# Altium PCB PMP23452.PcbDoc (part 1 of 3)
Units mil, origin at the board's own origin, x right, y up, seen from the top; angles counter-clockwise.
Board outline 4000 x 4000 mil, 6 copper layers (Top Layer, Layer 2, Layer 3, Layer 4, Layer 5, Bottom Layer), stack 40.224 mil thick; 235 components, 68 nets, 526 pads, 358 vias.
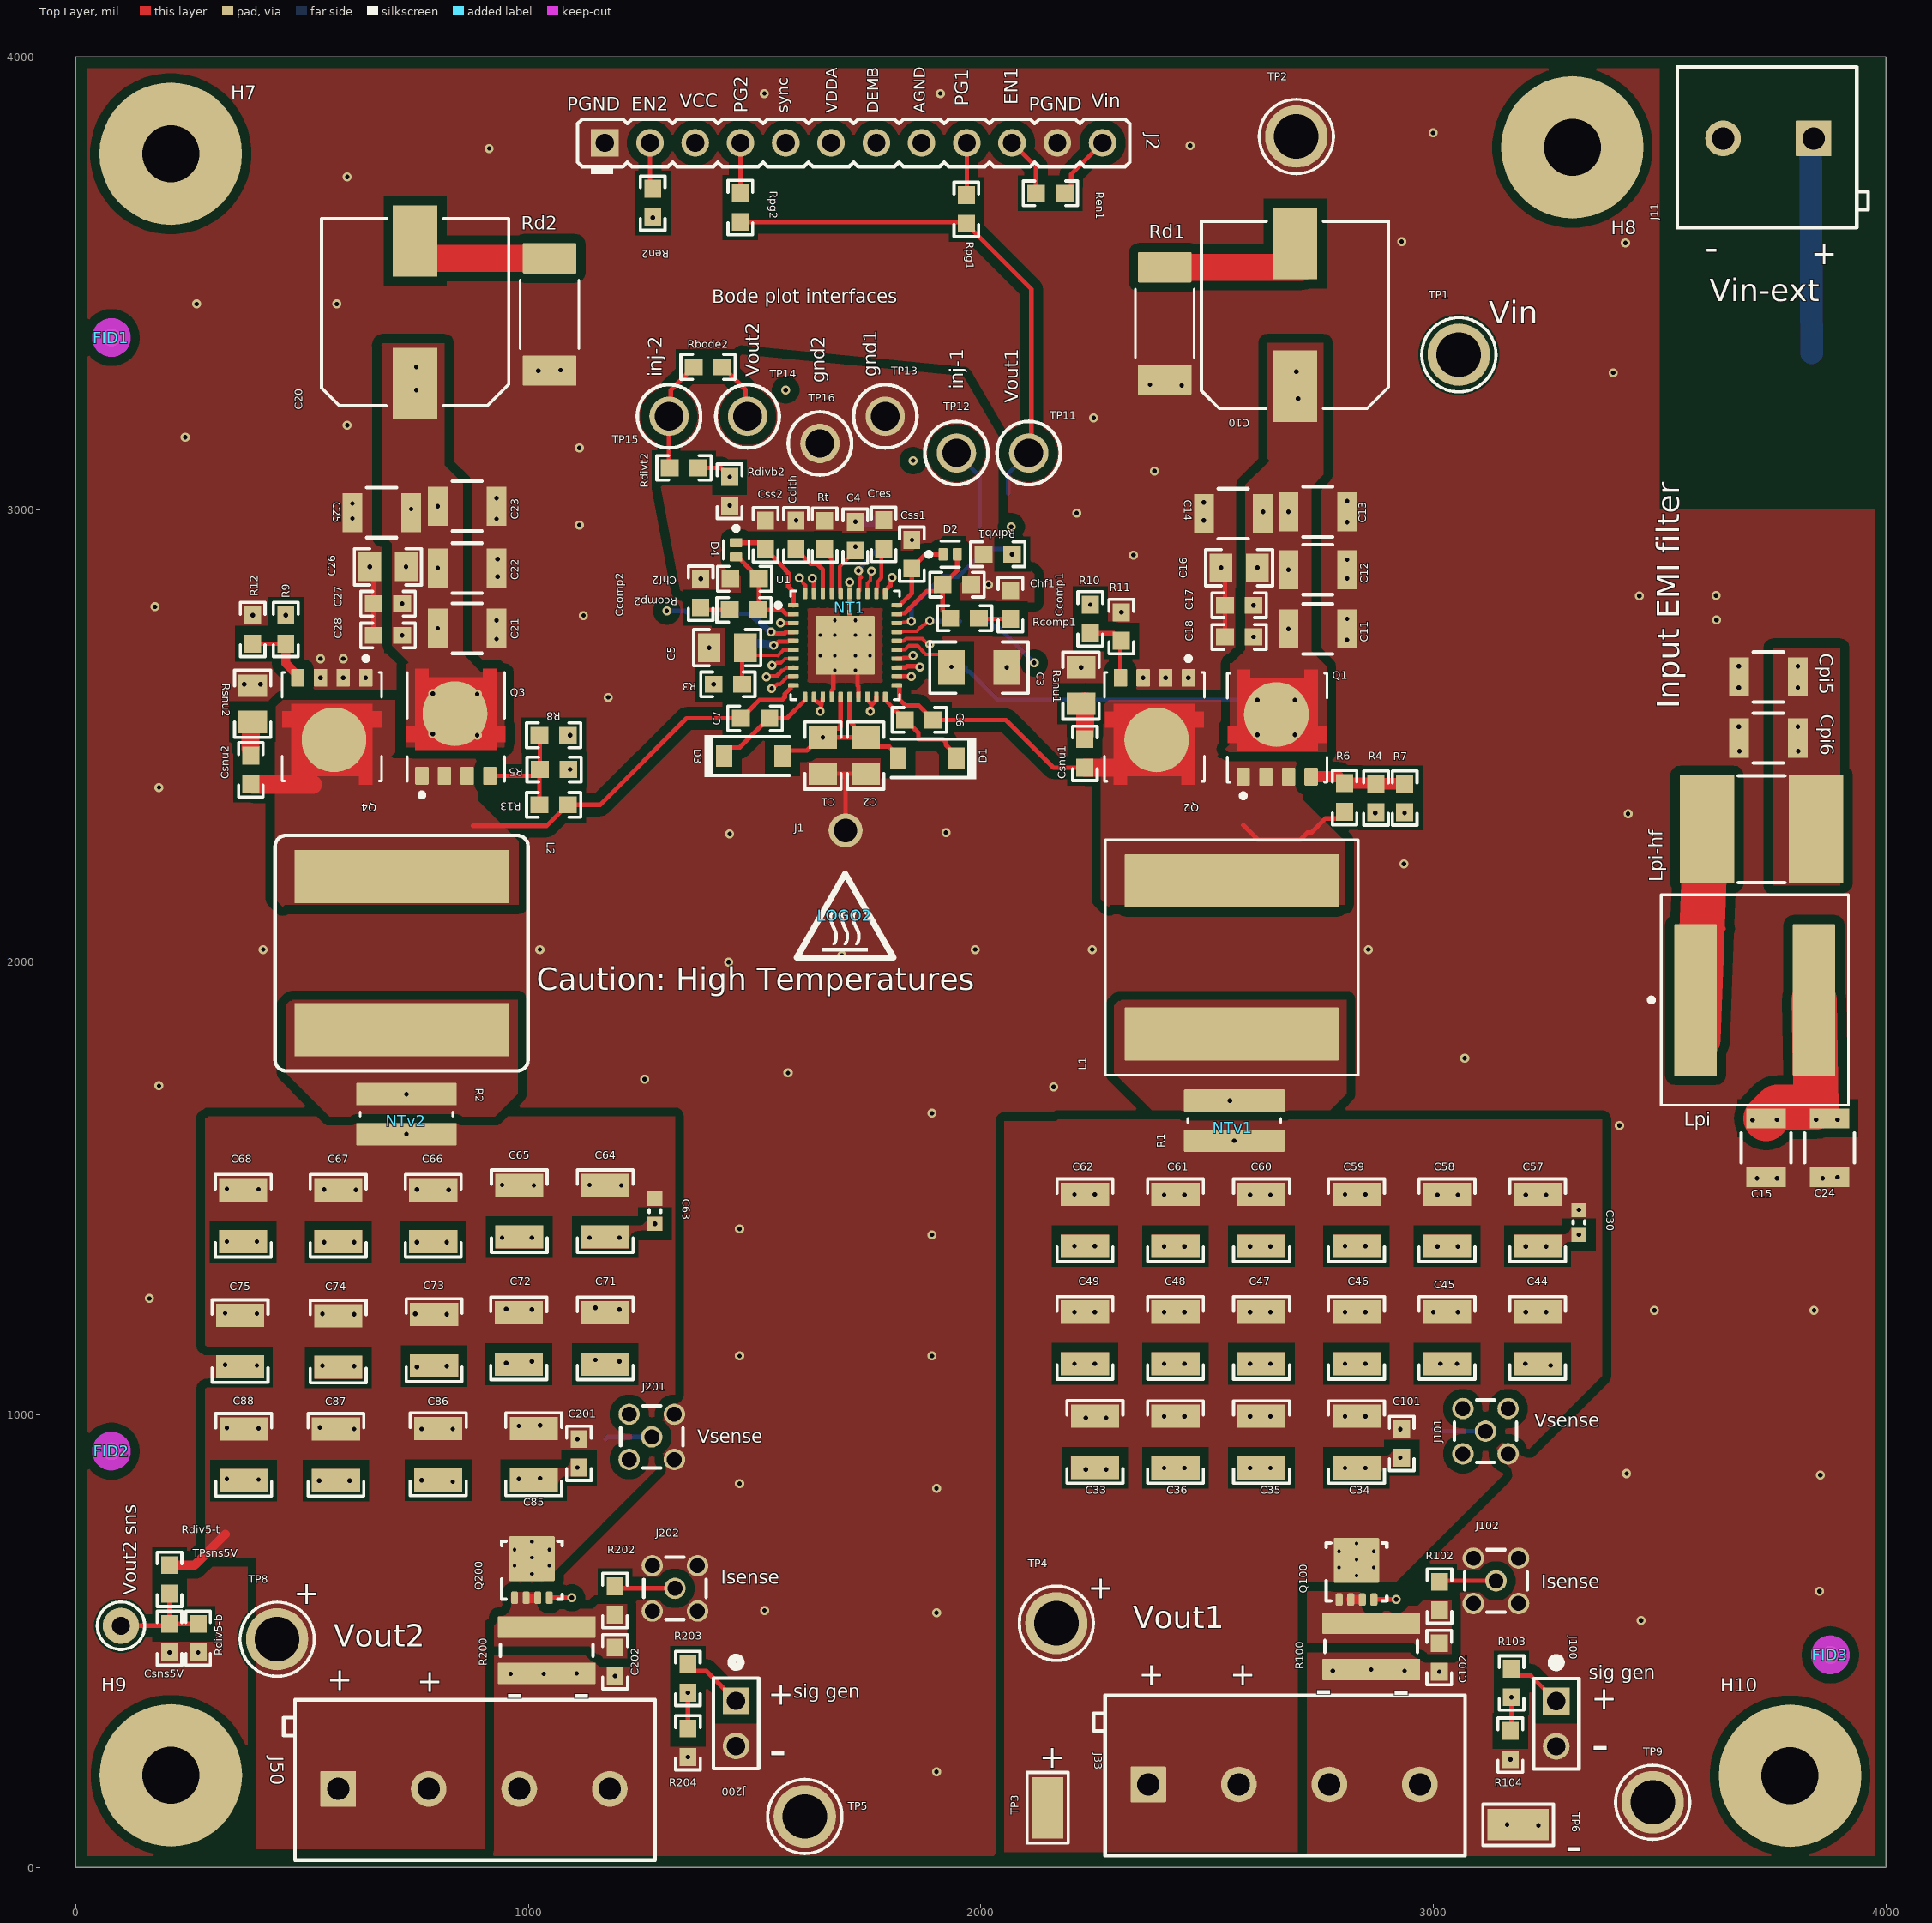
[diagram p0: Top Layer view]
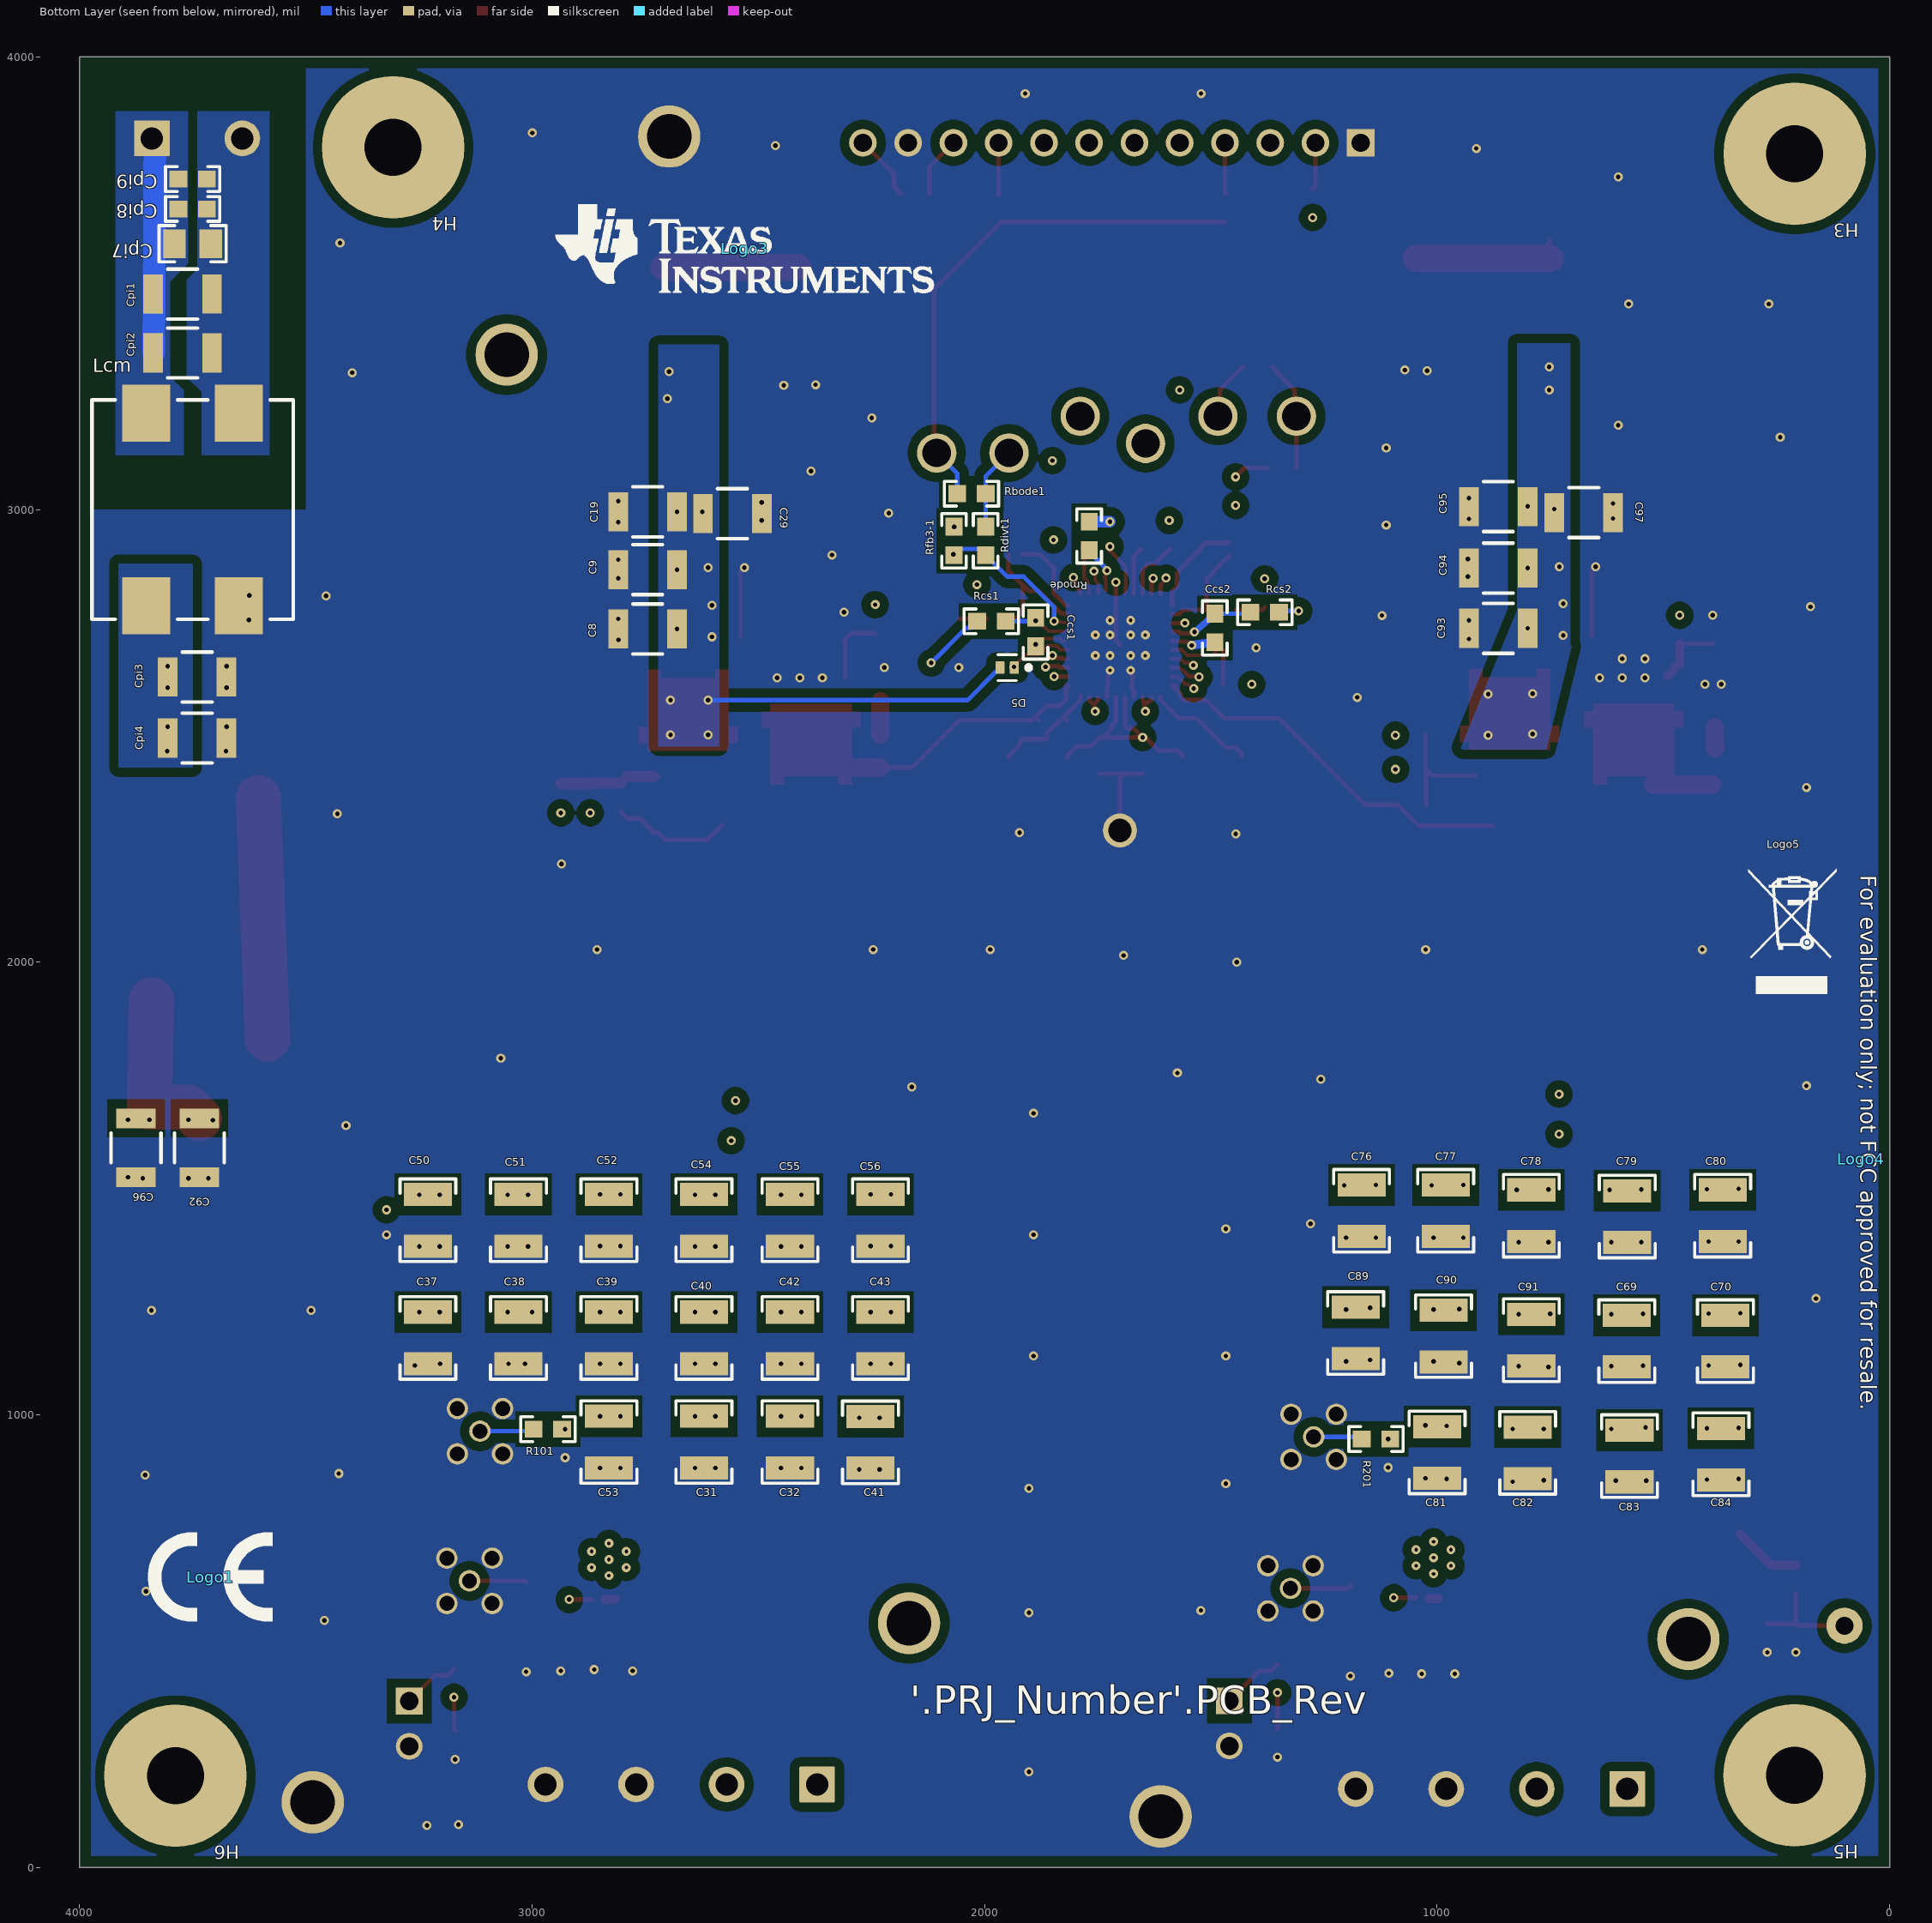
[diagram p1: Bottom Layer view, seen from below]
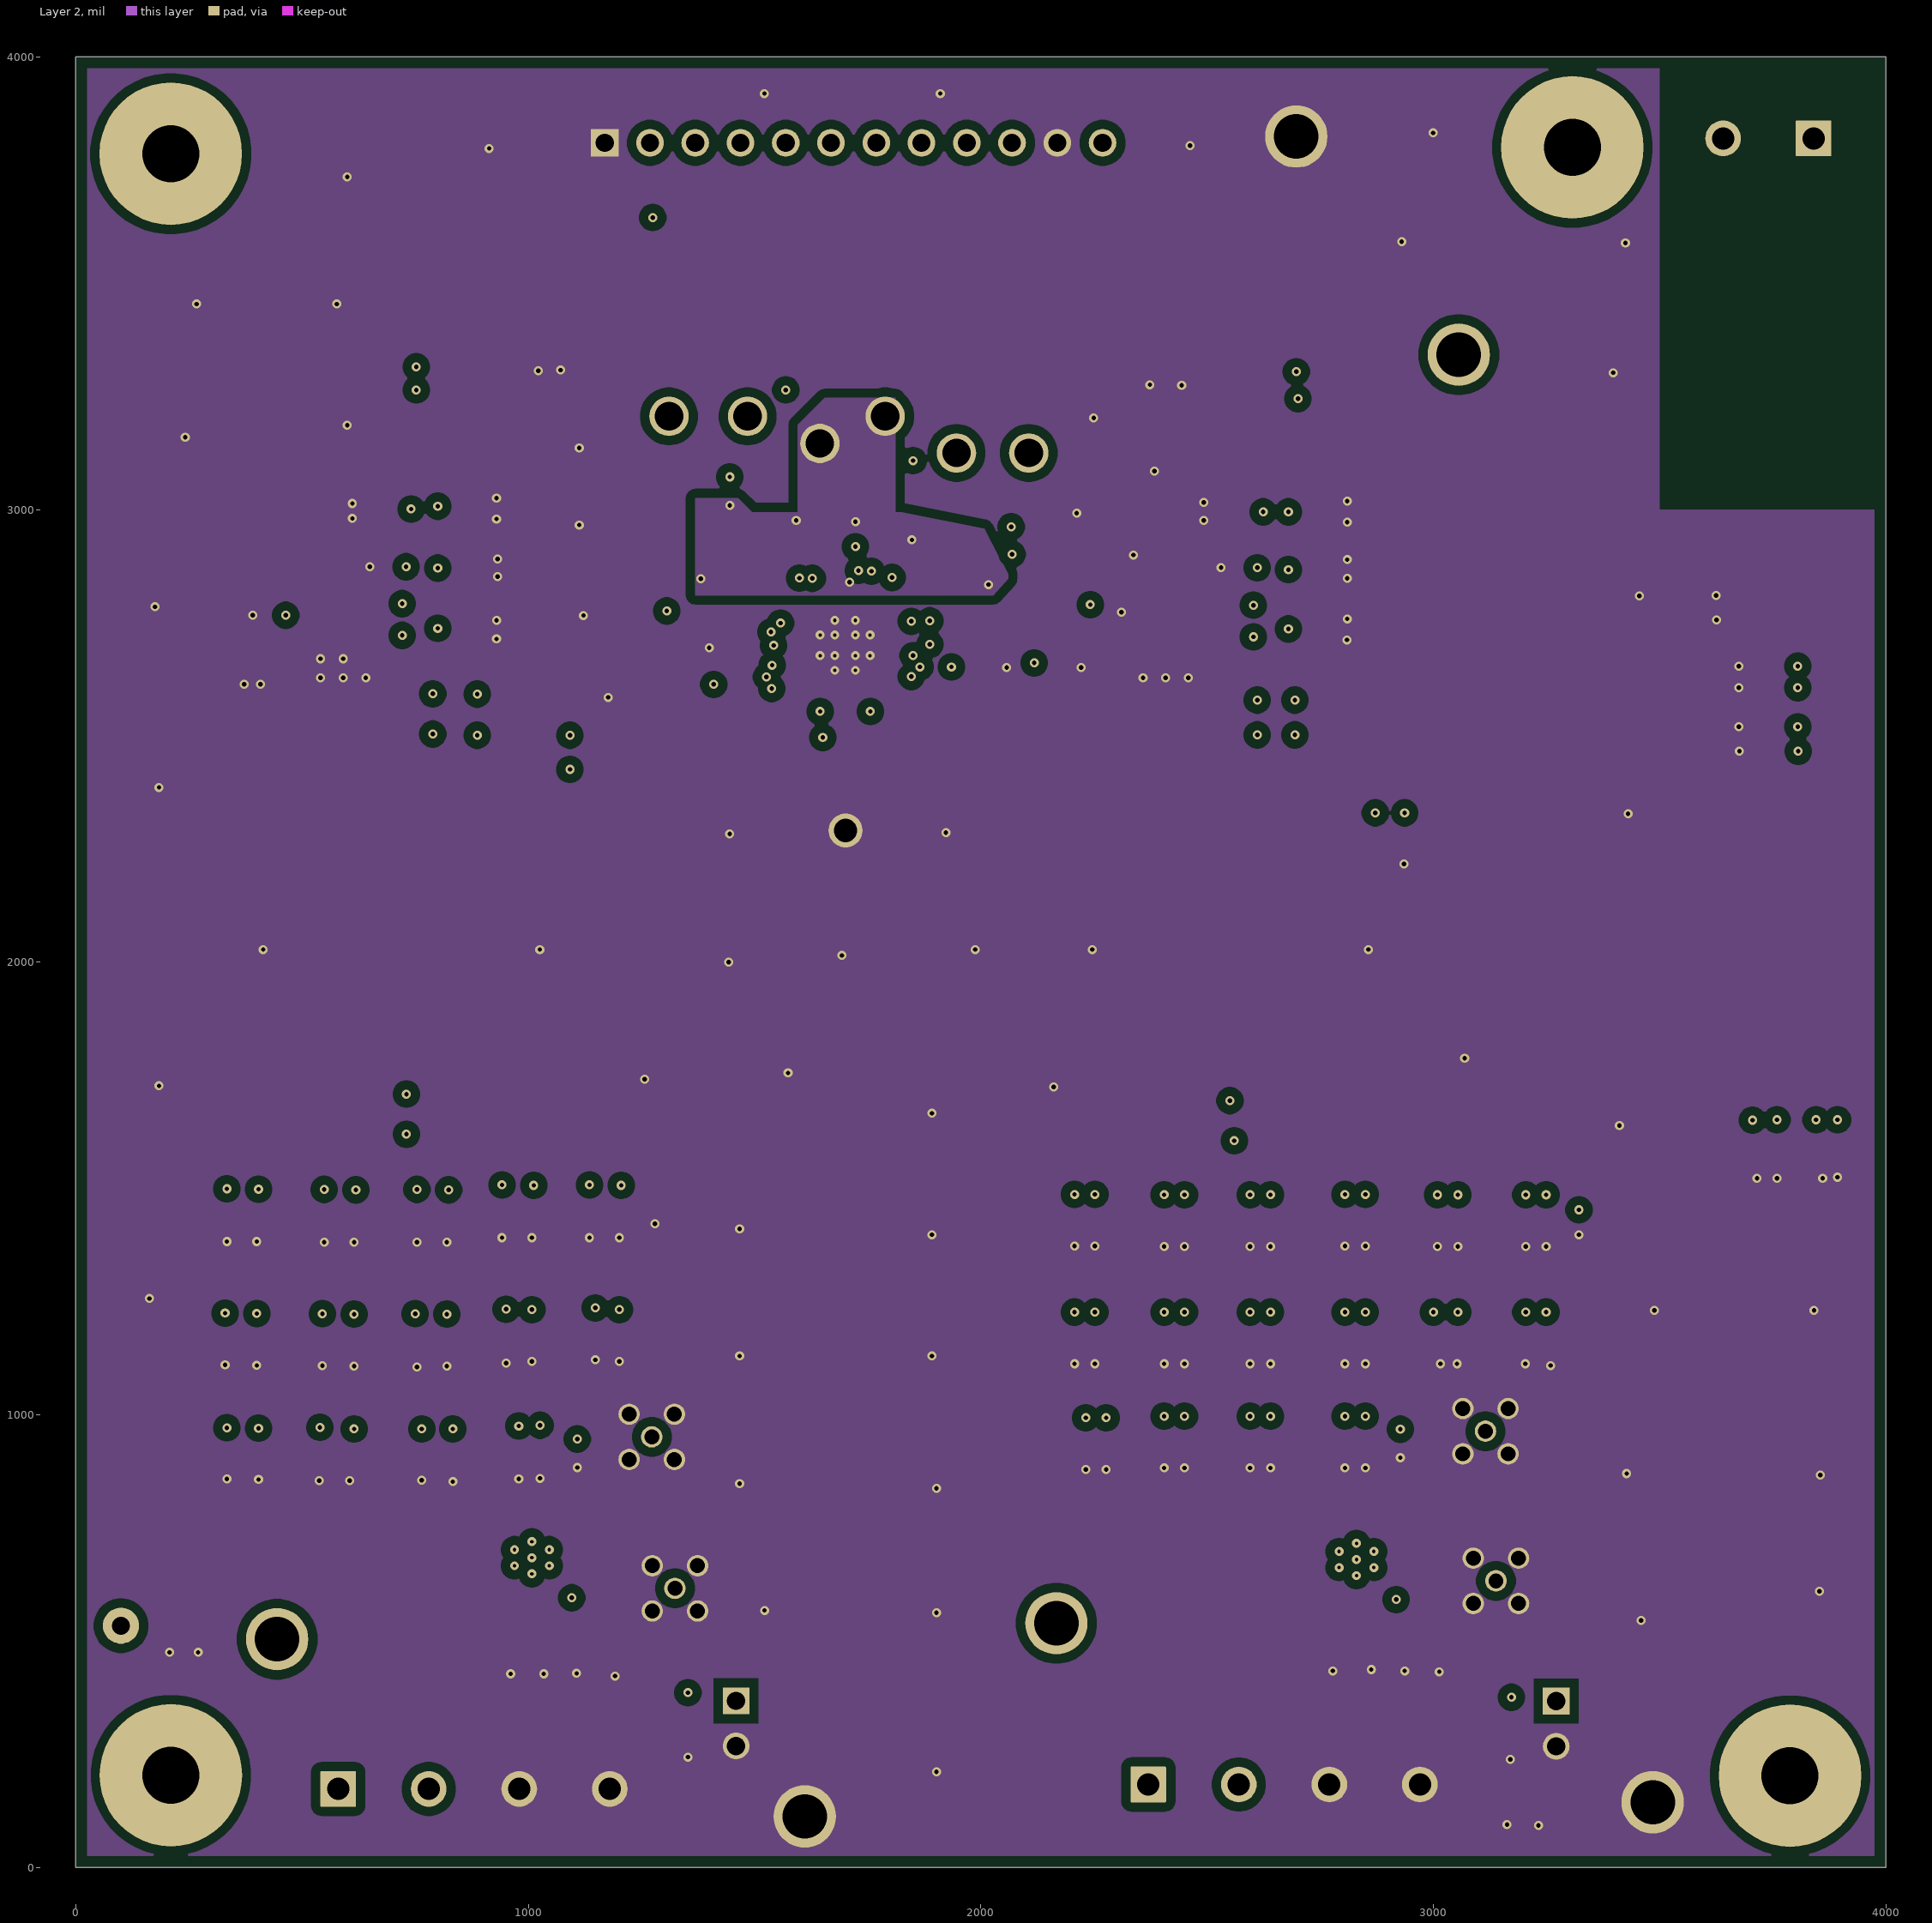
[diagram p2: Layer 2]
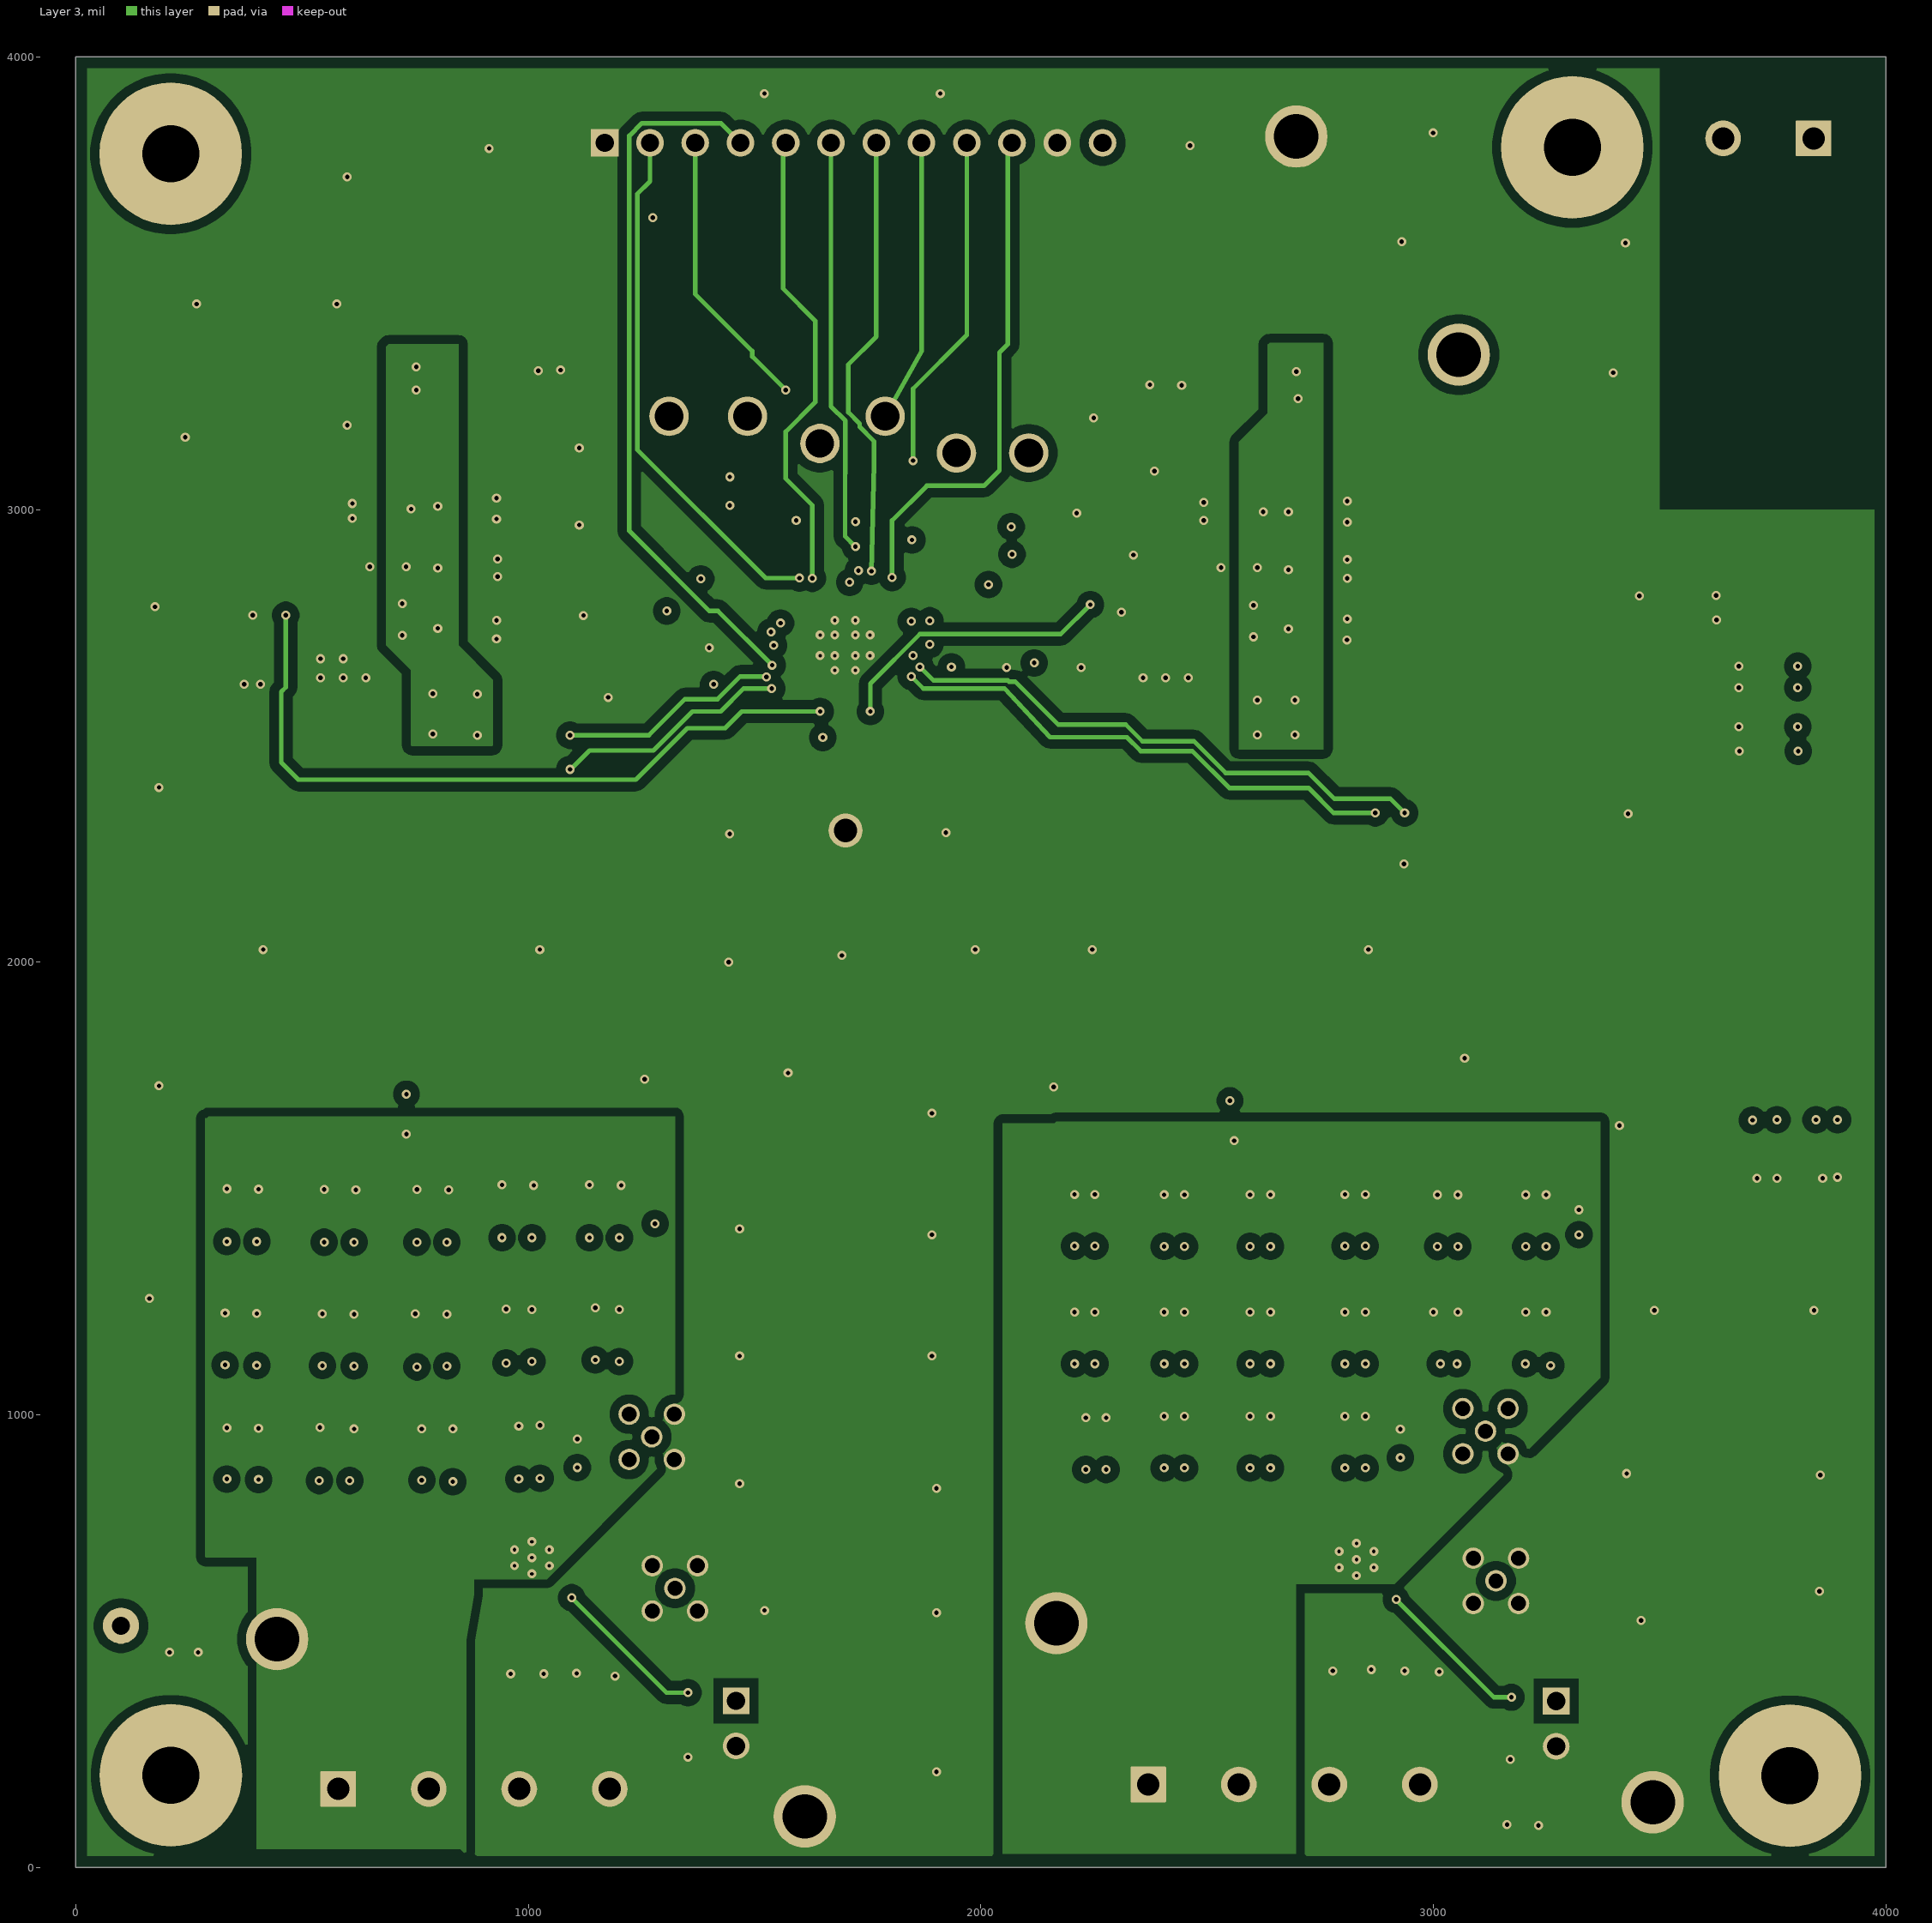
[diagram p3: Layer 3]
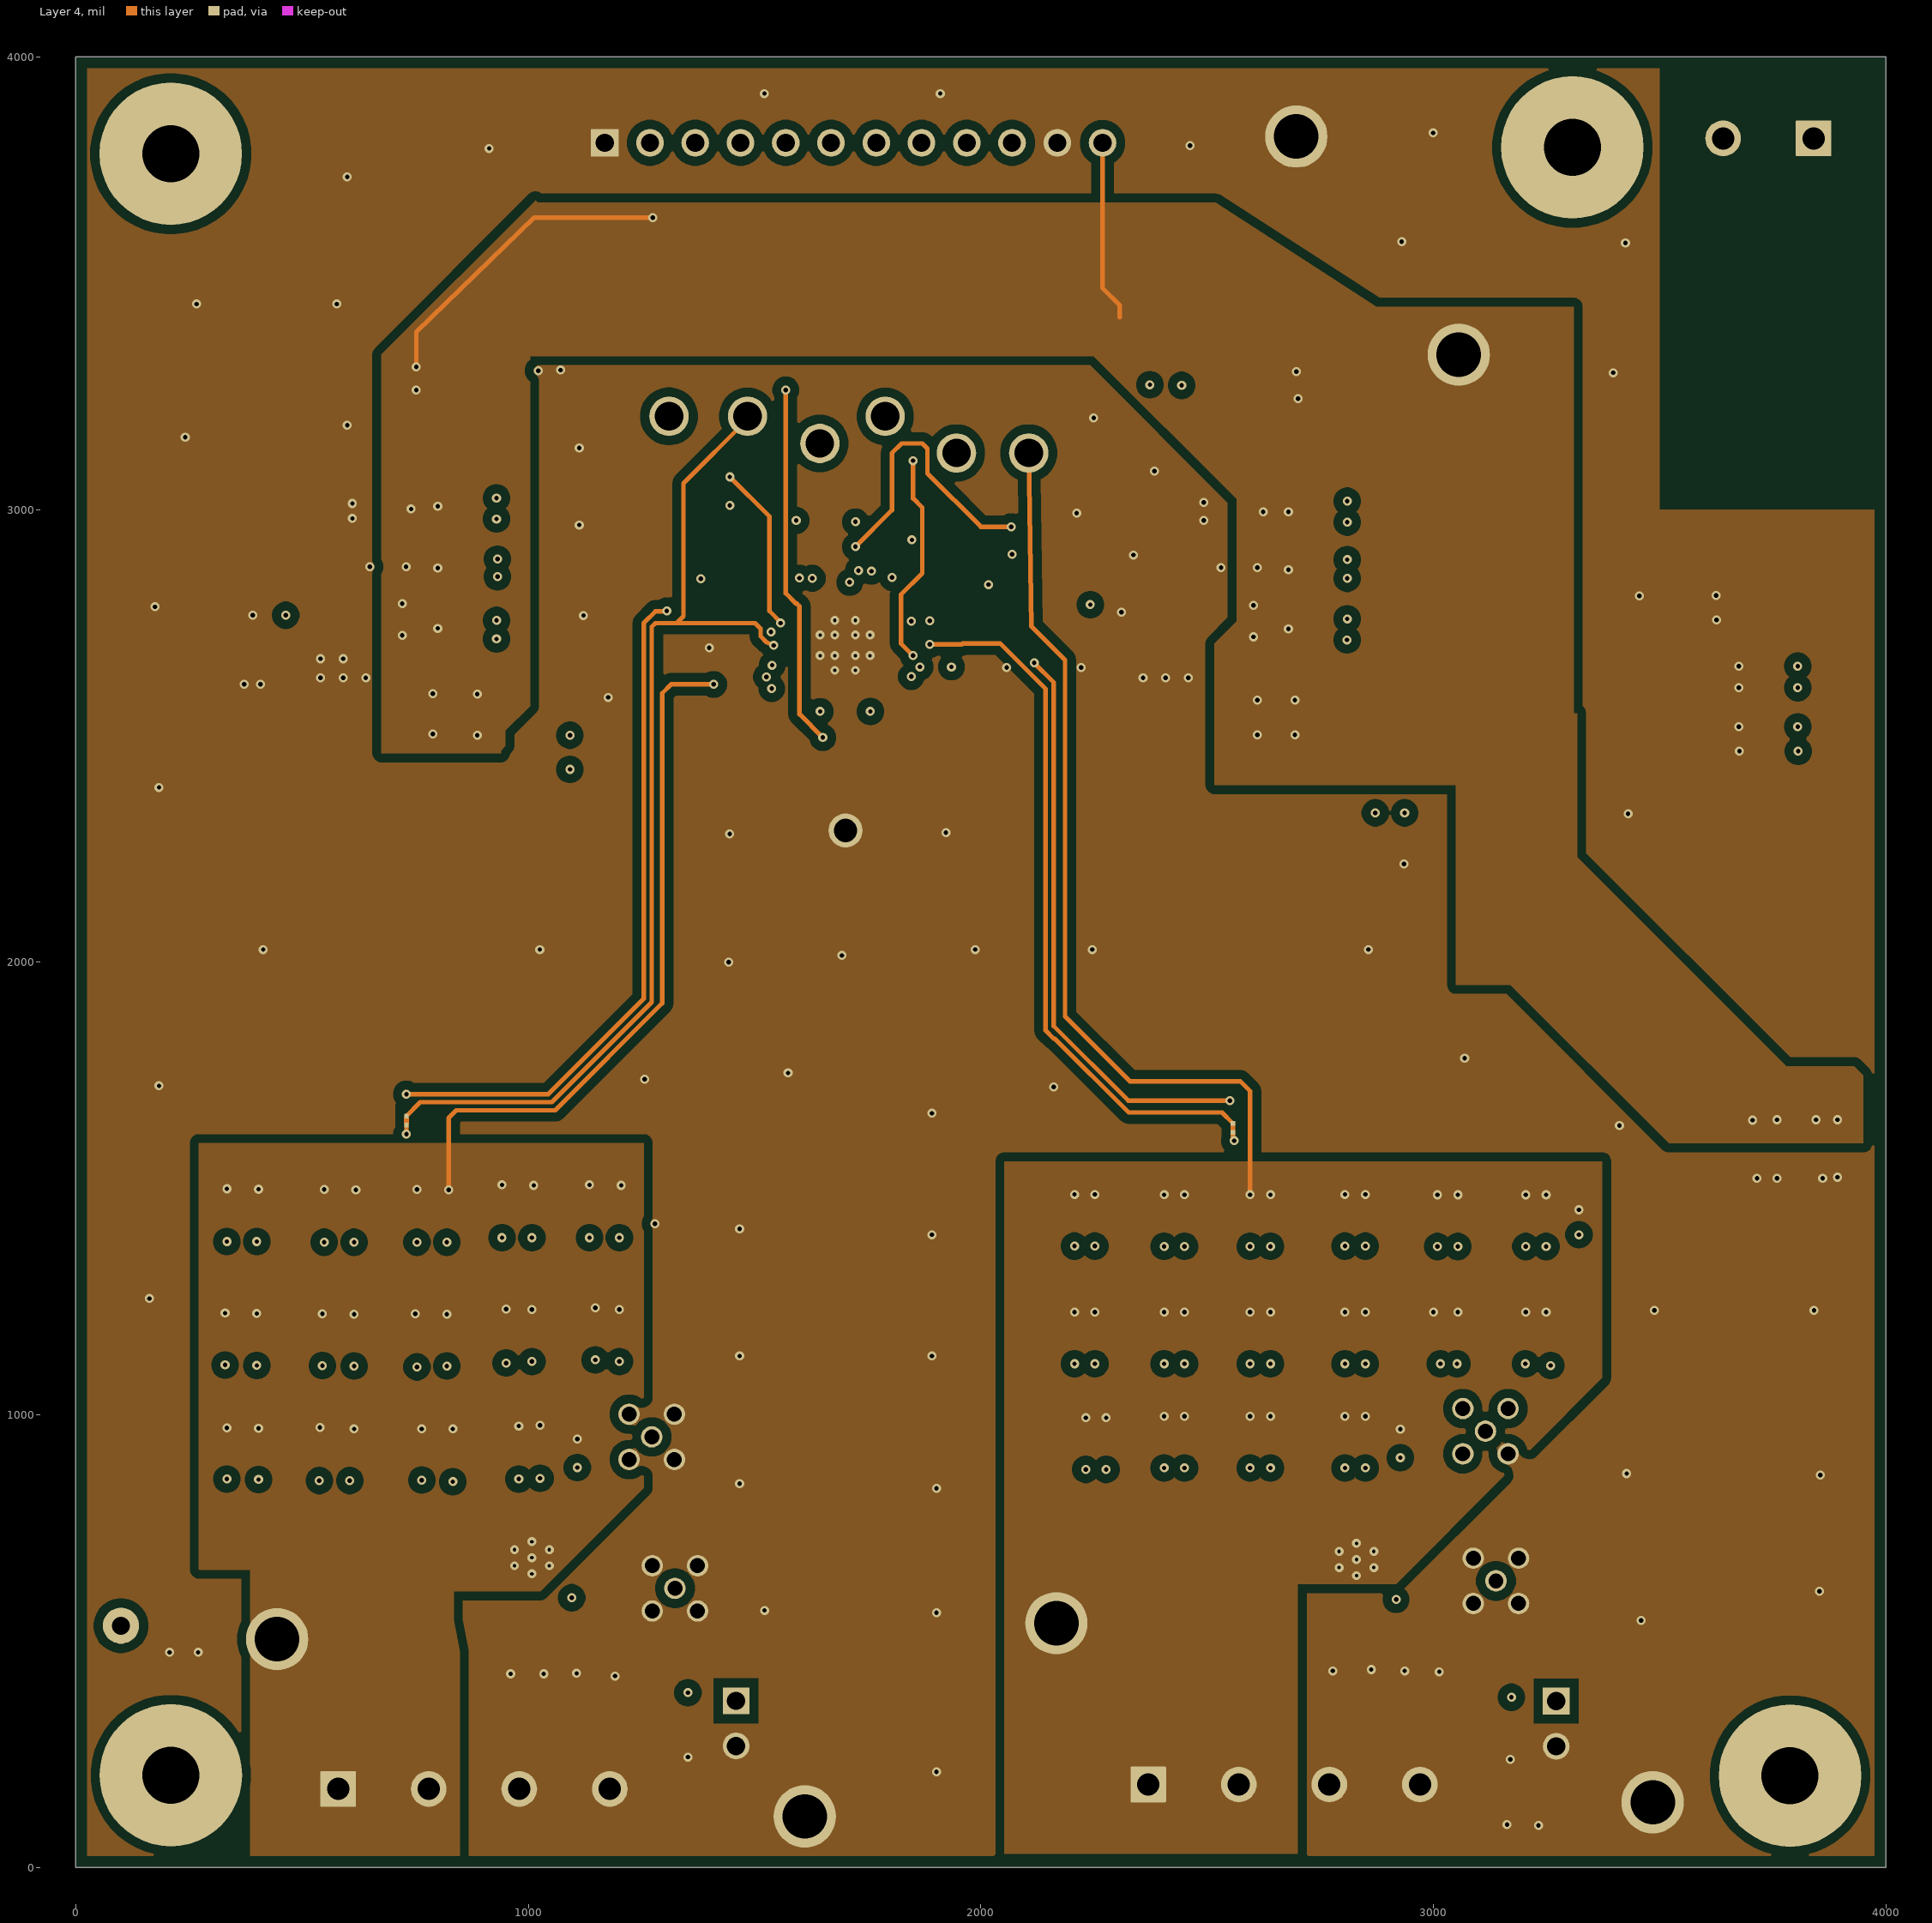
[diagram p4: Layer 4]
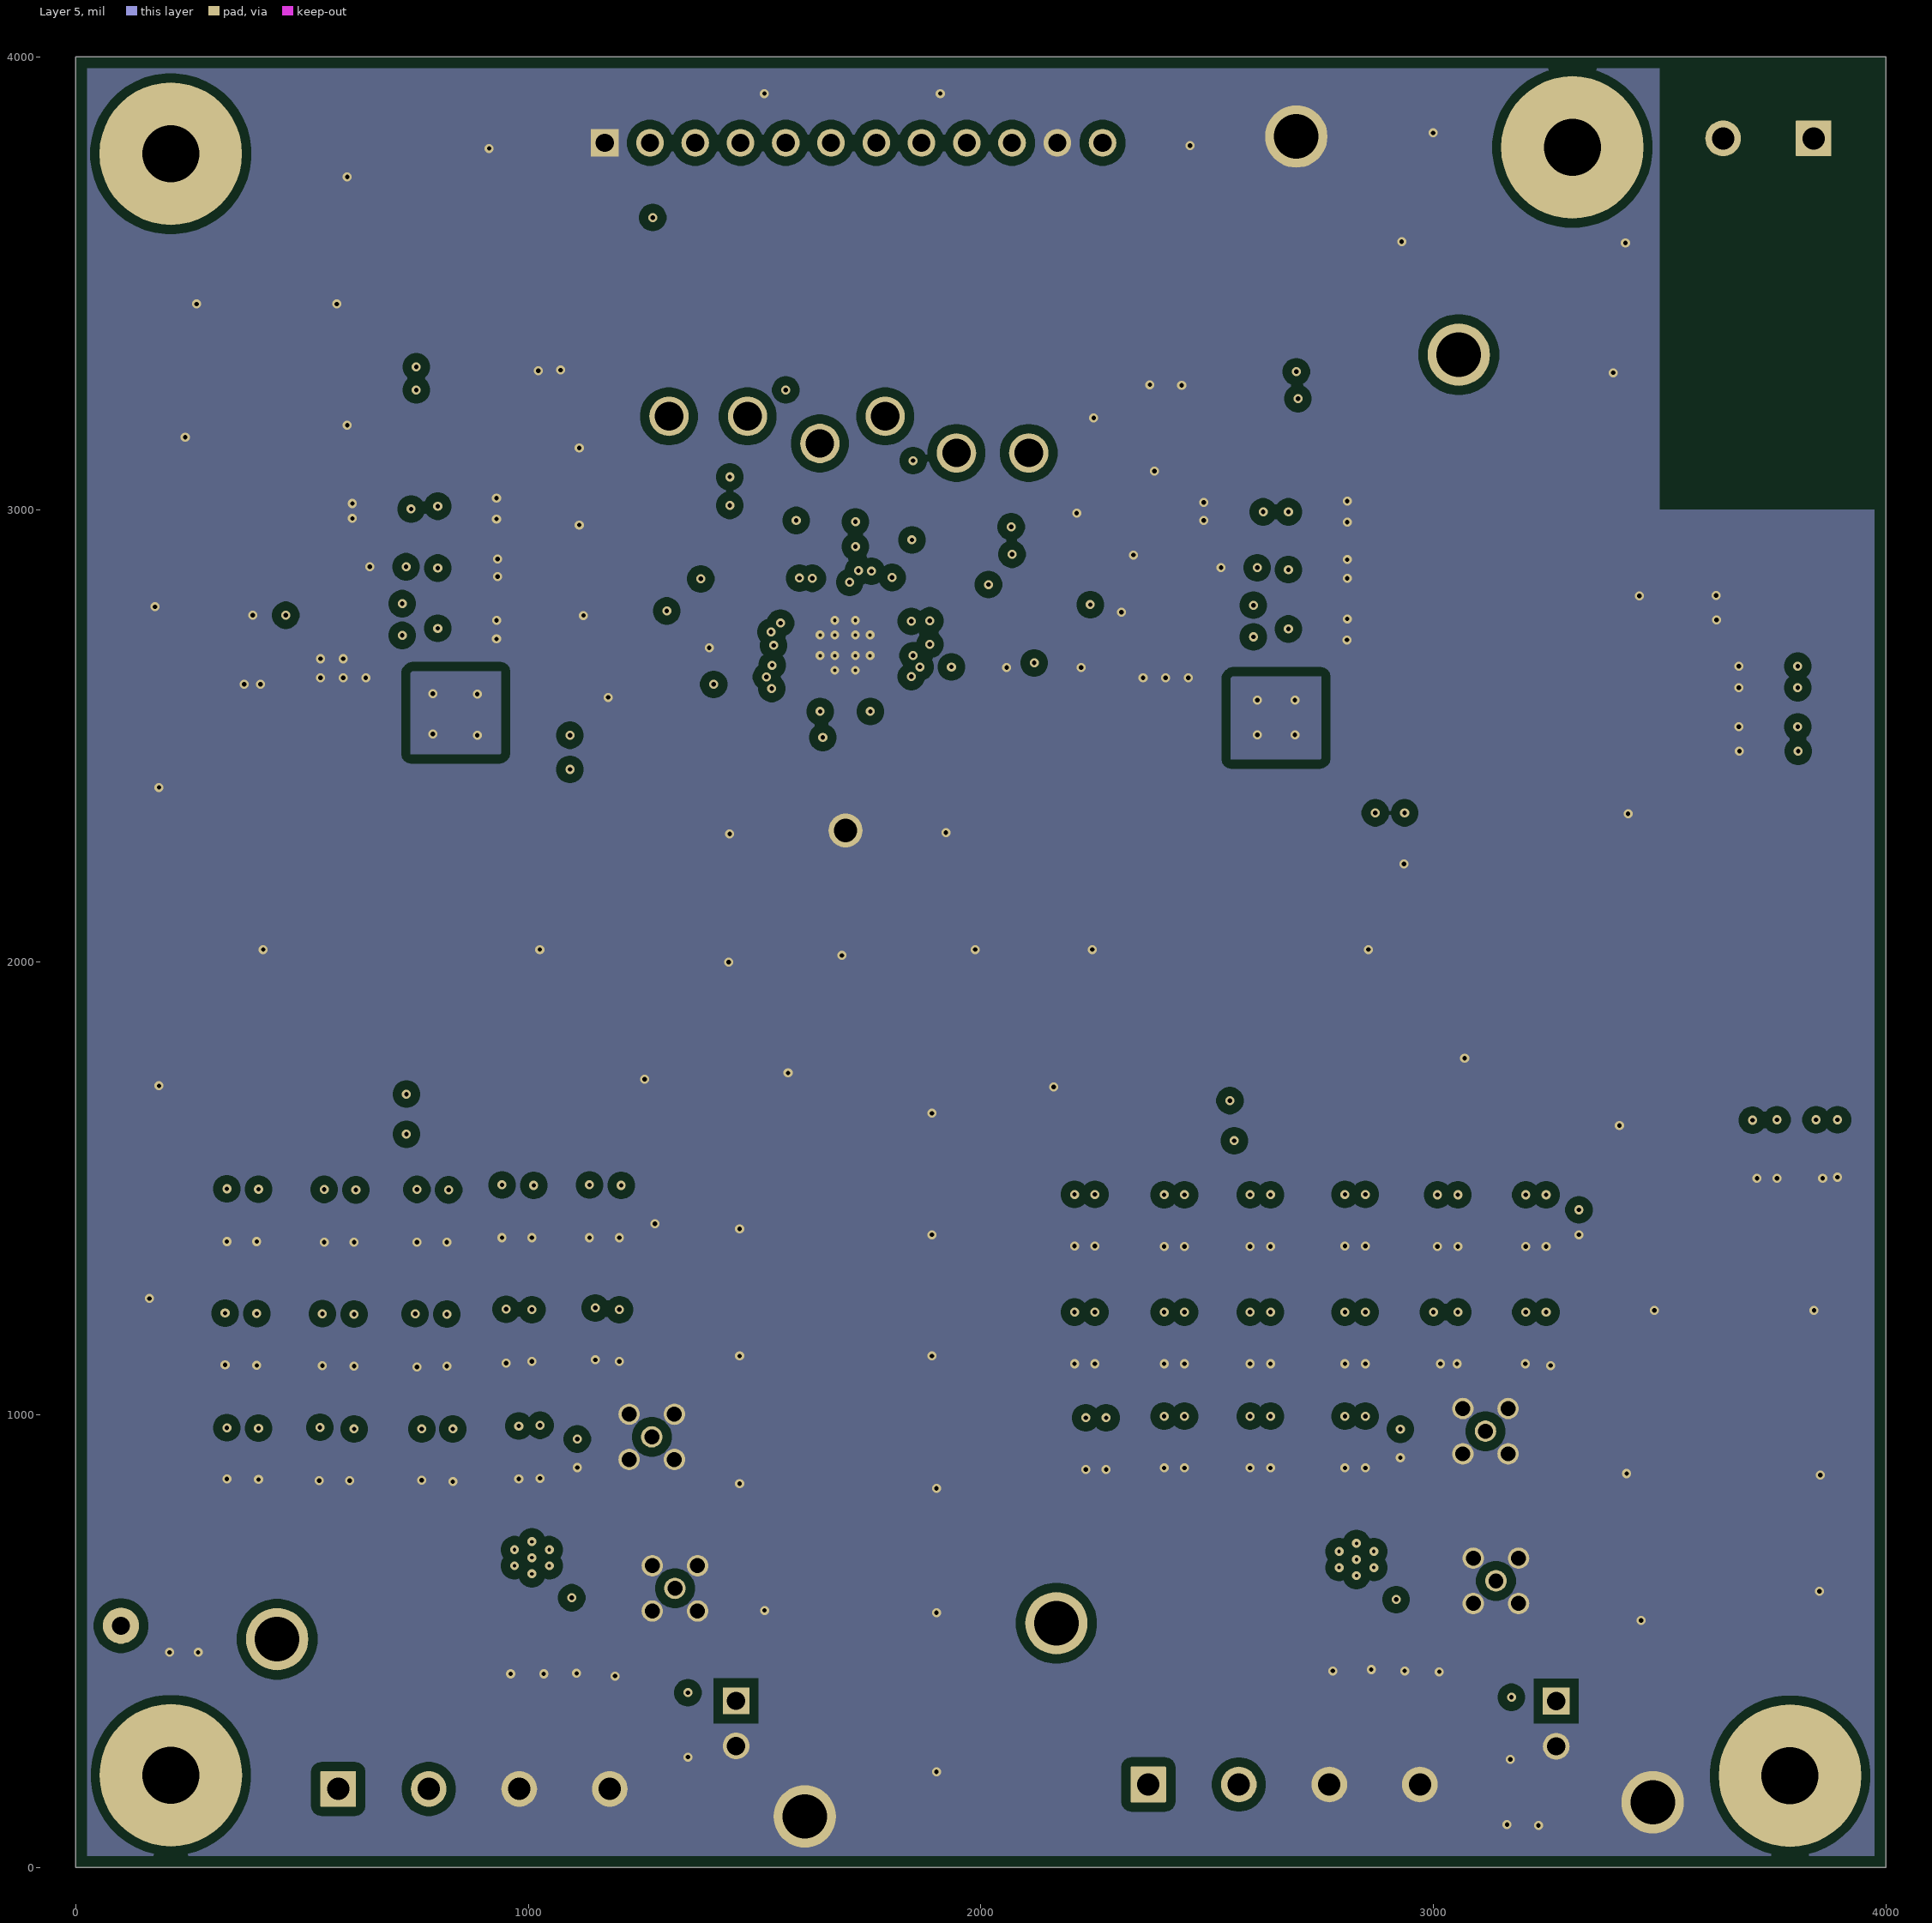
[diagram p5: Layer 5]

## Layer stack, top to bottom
Top Solder: solder mask 0.4, Solder Resist, Dk 3.5
Top Layer: signal copper 2.1
Dielectric 1: core 5, PP-006, Dk 4.1
Layer 2: signal copper 2.7559
Dielectric 2: prepreg 5, PP-006, Dk 4.1
Layer 3: signal copper 2.7559
Dielectric1: core 5, FR-4 High Tg, Dk 4.8
Layer 4: signal copper 2.7559
Dielectric 3: prepreg 5, PP-006, Dk 4.1
Layer 5: signal copper 2.7559
Dielectric 4: core 5, PP-006, Dk 4.1
Bottom Layer: signal copper 2.1
Bottom Solder: solder mask 0.4, Solder Resist, Dk 3.5

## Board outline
0,0 0,4000 4000,4000 4000,0

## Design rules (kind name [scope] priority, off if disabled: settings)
AcuteAngle [All] p1: minimum=4.50000000000000E+0001 checktracksonly=FALSE
AssemblyTestPointUsage [All] p1: valid=2
BoardOutlineClearance BoardOutlineClearance_MountingHoles [OnCopper and InComponentClass('Mounting Holes')] p1: gap=39.37 ignorepadtopadclearanceinfootprint=FALSE
BoardOutlineClearance BoardOutlineClearance_Poly [OnCopper and IsPoly] p2: gap=25 ignorepadtopadclearanceinfootprint=FALSE
BoardOutlineClearance [OnCopper and Not InComponentClass('Logo') and not InComponentClass('FiducialMark') and not InRegion(1000,500,4000,800) and not InPoly] p3: gap=40 ignorepadtopadclearanceinfootprint=FALSE
Clearance Clearance_Keepouts [((IsTrack Or IsArc) And Not InPoly) And IsFree and IsKeepOut vs ((IsTrack Or IsArc) And Not InPoly) And IsFree and IsKeepOut] p1: gap=0 ignorepadtopadclearanceinfootprint=FALSE
Clearance Clearance_Poly [InPolygon] p2: gap=20 ignorepadtopadclearanceinfootprint=TRUE
Clearance Clearance_FiducialMark [IsKeepOut and InComponentClass('FiducialMark') vs IsPad and InComponentClass('FiducialMark')] p3: gap=0 ignorepadtopadclearanceinfootprint=FALSE
Clearance [All] p4: gap=7.87 ignorepadtopadclearanceinfootprint=TRUE
ComponentClearance ComponentClearance_MountingHoles_FiducialMarks [InComponentClass('Mounting Holes') vs InComponentClass('FiducialMark')] p1: gap=50 collisioncheckmode=3 verticalgap=10 showdistances=FALSE
ComponentClearance ComponentClearance_Shunt [InComponentClass('Header') vs InComponentClass('Shunt')] p2: gap=0 collisioncheckmode=3 verticalgap=0 showdistances=FALSE
ComponentClearance ComponentClearance_Logo [InComponentClass('Logo')] p3: gap=30 collisioncheckmode=3 verticalgap=10 showdistances=FALSE
ComponentClearance ComponentClearance_ScrewToNut [(HasFootprint('NY PMS 440 0025 PH')) vs (HasFootprint('Keystone_1902C'))] p4: gap=5 collisioncheckmode=3 verticalgap=10 showdistances=FALSE
ComponentClearance ComponentClearance_MountingHoles [InComponentClass('Mounting Holes')] p5: gap=100 collisioncheckmode=3 verticalgap=100000 showdistances=FALSE
ComponentClearance ComponentClearance_SmallPassives [HasFootprint('0201*') or HasFootprint('0402*') or HasFootprint('0508') or HasFootprint('0603*') or HasFootprint('0612') or HasFootprint('0805*') or HasFootprint('0815*') or HasFootprint('0830*') or HasFootprint('1206*') or HasFootprint('1210*') or HasFootprint('1808*') or HasFootprint('1812*') or HasFootprint('1825*') or HasFootprint('2010*') or HasFootprint('2220*') or HasFootprint('2225*') or HasFootprint('2512*') or HasFootprint('2728*') or HasFootprint('3518*') vs HasFootprint('0201*') or HasFootprint('0402*') or HasFootprint('0508') or HasFootprint('0603*') or HasFootprint('0612') or HasFootprint('0805*') or HasFootprint('0815*') or HasFootprint('0830*') or HasFootprint('1206*') or HasFootprint('1210*') or HasFootprint('1808*') or HasFootprint('1812*') or HasFootprint('1825*') or HasFootprint('2010*') or HasFootprint('2220*') or HasFootprint('2225*') or HasFootprint('2512*') or HasFootprint('2728*') or HasFootprint('3518*')] p6: gap=14.96 collisioncheckmode=3 verticalgap=10 showdistances=FALSE
ComponentClearance ComponentClearance_THtoSMT [IsThruComponent vs IsSMTComponent] p7: gap=30 collisioncheckmode=3 verticalgap=30 showdistances=FALSE
ComponentClearance ComponentClearance_THtoTH [IsThruComponent vs IsThruComponent] p8: gap=20 collisioncheckmode=3 verticalgap=30 showdistances=FALSE
ComponentClearance [All] p9: gap=20 collisioncheckmode=3 verticalgap=10 showdistances=FALSE donotcheckwithout3dbody=TRUE
DiffPairsRouting [All] p1: maxlimit=100 minlimit=10 mostfreqgap=10 toplayer_minwidth=15 toplayer_maxwidth=15 toplayer_prefwidth=15 midlayer1_minwidth=15 midlayer1_maxwidth=15 midlayer1_prefwidth=15 midlayer2_minwidth=15 midlayer2_maxwidth=15 midlayer2_prefwidth=15 midlayer3_minwidth=15 midlayer3_maxwidth=15 midlayer3_prefwidth=15 midlayer4_minwidth=15 midlayer4_maxwidth=15 midlayer4_prefwidth=15 bottomlayer_minwidth=15 bottomlayer_maxwidth=15 bottomlayer_prefwidth=15 maxuncoupledlength=1000
FabricationTestPointUsage TestPointUsage [All] p1: valid=2 allowmultiple=FALSE
FabricationTestpoint Testpoint [All] p1: side=3 testpointundercomponent=TRUE minsize=40 maxsize=100 preferedsize=60 minholesize=0 maxholesize=40 preferedholesize=32 testpointgrid=1 allowsidetop=TRUE allowsidebottom=TRUE usegrid=TRUE gridtolerance=0.01
FanoutControl Fanout_LCC [IsLCC] p1: bgadir=Out bgaviamode=Centered fanoutstyle=Auto fanoutdirection=Alternating viagrid=1 // Fanout_LCC (Default Rule)
FanoutControl Fanout_BGA [IsBGA] p2: bgadir=Out bgaviamode=Centered fanoutstyle=Auto fanoutdirection=Alternating viagrid=1 // Fanout_BGA (Default Rule)
FanoutControl Fanout_Default [All] p4: bgadir=Out bgaviamode=Centered fanoutstyle=Auto fanoutdirection=Alternating viagrid=1 // Fanout_Default (Default Rule)
FanoutControl Fanout_Small [(CompPinCount < 5)] p5: bgadir=Out bgaviamode=Centered fanoutstyle=Auto fanoutdirection=OutThenIn viagrid=1 // Fanout_Small (Default Rule)
HoleSize [All] p1: absolutevalues=TRUE maxlimit=251 minlimit=7.87 maxpercent=80.000 minpercent=20.000
MinimumAnnularRing MinimumAnnularRing_ThermalPadVias [IsVia and InAnyComponent] p1: minimumring=5.91
MinimumAnnularRing [All] p2: minimumring=4.9
MinimumSolderMaskSliver MinimumSolderMaskSliver_Logo [InComponentClass('Logo') vs InComponentClass('Logo')] p1: minsoldermaskwidth=0.7
MinimumSolderMaskSliver [All] p2: minsoldermaskwidth=3.94
PlaneConnect [All] p1: planeconnectstyle=Relief reliefexpansion=10 reliefentries=4 reliefconductorwidth=10 reliefairgap=10
PolygonConnect PolygonConnect_19 [All vs IsNamedPolygon('BOTTOM_LAYER_VIN-EXT_P014')] p1: connectstyle=Direct reliefconductorwidth=10 reliefentries=4 polygonreliefangle="90 Angle" airgapwidth=10
PolygonConnect PolygonConnect_18 [All vs IsNamedPolygon('BOTTOM_LAYER_PGND-EXT_P015')] p2: connectstyle=Direct reliefconductorwidth=10 reliefentries=4 polygonreliefangle="90 Angle" airgapwidth=10
PolygonConnect PolygonConnect_17 [All vs IsNamedPolygon('LAYER_5_PGND_P013')] p3: connectstyle=Direct reliefconductorwidth=10 reliefentries=4 polygonreliefangle="90 Angle" airgapwidth=10
PolygonConnect PolygonConnect_16 [All vs IsNamedPolygon('TOP_LAYER_NETC102_2_P012')] p4: connectstyle=Direct reliefconductorwidth=10 reliefentries=4 polygonreliefangle="90 Angle" airgapwidth=10
PolygonConnect PolygonConnect_15 [All vs IsNamedPolygon('TOP_LAYER_NETC6_1_P011')] p5: connectstyle=Direct reliefconductorwidth=10 reliefentries=4 polygonreliefangle="90 Angle" airgapwidth=10
PolygonConnect PolygonConnect_14 [All vs IsNamedPolygon('TOP_LAYER_NETL1_1_P010')] p6: connectstyle=Direct reliefconductorwidth=10 reliefentries=4 polygonreliefangle="90 Angle" airgapwidth=10
PolygonConnect PolygonConnect_13 [All vs IsNamedPolygon('TOP_LAYER_3.3V_P009')] p7: connectstyle=Direct reliefconductorwidth=10 reliefentries=4 polygonreliefangle="90 Angle" airgapwidth=10
PolygonConnect PolygonConnect_12 [All vs IsNamedPolygon('TOP_LAYER_NETC202_2_P008')] p8: connectstyle=Direct reliefconductorwidth=10 reliefentries=4 polygonreliefangle="90 Angle" airgapwidth=10
PolygonConnect PolygonConnect_11 [All vs IsNamedPolygon('TOP_LAYER_5V_P007')] p9: connectstyle=Direct reliefconductorwidth=10 reliefentries=4 polygonreliefangle="90 Angle" airgapwidth=10
PolygonConnect PolygonConnect_10 [All vs IsNamedPolygon('TOP_LAYER_NETL2_2_P006')] p10: connectstyle=Direct reliefconductorwidth=10 reliefentries=4 polygonreliefangle="90 Angle" airgapwidth=10
PolygonConnect PolygonConnect_9 [All vs IsNamedPolygon('TOP_LAYER_NETC7_1_P005')] p11: connectstyle=Direct reliefconductorwidth=10 reliefentries=4 polygonreliefangle="90 Angle" airgapwidth=10
PolygonConnect PolygonConnect_8 [All vs IsNamedPolygon('LAYER_4_VIN_P004')] p12: connectstyle=Direct reliefconductorwidth=10 reliefentries=4 polygonreliefangle="90 Angle" airgapwidth=10
PolygonConnect PolygonConnect_7 [All vs IsNamedPolygon('LAYER_4_VIN_P004')] p13: connectstyle=Direct reliefconductorwidth=10 reliefentries=4 polygonreliefangle="90 Angle" airgapwidth=10
PolygonConnect PolygonConnect_6 [All vs IsNamedPolygon('LAYER_2_PGND_P002')] p14: connectstyle=Direct reliefconductorwidth=10 reliefentries=4 polygonreliefangle="90 Angle" airgapwidth=10
PolygonConnect PolygonConnect_5 [All vs IsNamedPolygon('LAYER_2_PGND_P002')] p15: connectstyle=Direct reliefconductorwidth=10 reliefentries=4 polygonreliefangle="90 Angle" airgapwidth=10
PolygonConnect PolygonConnect_4 [All vs IsNamedPolygon('TOP_LAYER_AGND_P000')] p16: connectstyle=Direct reliefconductorwidth=10 reliefentries=4 polygonreliefangle="90 Angle" airgapwidth=10
PolygonConnect PolygonConnect_3 [All vs IsNamedPolygon('LAYER_2_AGND_P001')] p17: connectstyle=Direct reliefconductorwidth=10 reliefentries=4 polygonreliefangle="90 Angle" airgapwidth=10
PolygonConnect PolygonConnect_2 [All vs IsNamedPolygon('TOP_LAYER_AGND_P000')] p18: connectstyle=Direct reliefconductorwidth=10 reliefentries=4 polygonreliefangle="90 Angle" airgapwidth=10
PolygonConnect PolygonConnect_1 [All vs IsNamedPolygon('TOP_LAYER_AGND_P000')] p19: thpad.connectstyle=Direct thpad.reliefconductorwidth=10 thpad.reliefentries=4 thpad.polygonreliefangle="90 Angle" thpad.airgapwidth=10 smdpad.connectstyle=Direct smdpad.reliefconductorwidth=10 smdpad.reliefentries=4 smdpad.polygonreliefangle="90 Angle" smdpad.airgapwidth=10 via.connectstyle=Relief via.reliefconductorwidth=10 via.reliefentries=4 via.polygonreliefangle="90 Angle" via.airgapwidth=10
PolygonConnect [All] p20: connectstyle=Direct reliefconductorwidth=10 reliefentries=4 polygonreliefangle="90 Angle" airgapwidth=10
RoutingLayers [All] p1: top layer_v5=TRUE mid layer 1_v5=FALSE mid layer 2_v5=TRUE mid layer 3_v5=TRUE mid layer 4_v5=FALSE bottom layer_v5=TRUE
RoutingVias ThermalPadVias [IsVia and InAnyComponent] p1: holewidth=7.87 width=19.68 viastyle="Through Hole" minholewidth=7.87 minwidth=19.68 maxholewidth=12.99 maxwidth=23.62
RoutingVias [All] p2: holewidth=10 width=20 viastyle="Through Hole" minholewidth=7.87 minwidth=18 maxholewidth=40 maxwidth=65
SilkToBoardRegionClearance [Not ((IsComment or IsDesignator) And (Hide <> 'False')) and not InRegion(1000,500,4000,800)] p1:
SilkToSilkClearance SilkToSilkClearance_Pb-FreeLogo [(HasFootprint('Pb-Free_Overlay_Medium') OR HasFootprint('Pb-Free_Overlay_Small')) vs (HasFootprint('Pb-Free_Overlay_Medium') OR HasFootprint('Pb-Free_Overlay_Small'))] p1: silktosilkclearance=0
SilkToSilkClearance [All] p2: silktosilkclearance=3.94
SilkToSolderMaskClearance SilkToComponentPadClearance [(IsPad or IsFill or IsRegion) and InAnycomponent] p1: minsilkscreentomaskgap=5 clearancetoexposedcopper=TRUE
SilkToSolderMaskClearance "Silk to Solder Mask Opening" [All] p2: minsilkscreentomaskgap=3.94 clearancetoexposedcopper=FALSE
SolderMaskExpansion [All] p1: expansion=1.97 istentingtop=FALSE
UnRoutedNet [All] p1: checkbadconnections=TRUE
Width [All] p1: maxlimit=100 minlimit=6 preferedwidth=10 checkconnectedcopper=TRUE
13 further rules are at their usual default settings.

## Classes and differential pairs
net class Vin: NetC3_1 NetCpi3_1 NetLpi-hf_2 VIN VIN-ext
net class SW2: NetC7_1 NetC7_2 NetQ3_4 NetR5_1 NetR8_1
net class SW1: NetC6_1 NetC6_2 NetQ1_4 NetR4_1 NetR7_1
net class LV: 3.3V 5V AGND COMP1 COMP2 DEMB EN1 EN2 FB1 FB2 NetC5_1 NetC10_2 NetC20_2 NetC102_2 NetC202_2 NetCcomp2_1 NetCcs1_1 NetCcs1_2 NetCcs2_1 NetCcs2_2 NetCdith_1 NetCres_1 NetCsnu1_2 NetCsnu2_2 NetJ100_1 NetJ101_1 NetJ102_1 NetJ200_1 NetJ201_1 NetJ202_1 NetL1_1 NetL2_2 NetQ2_4 NetQ4_4 NetQ100_4 NetQ200_4 NetR9_1 NetR10_1 NetRbode2_1 NetRmode_2 NetRt_2 PG1 PG2 PGND PGND-ext SS1 SS2 SYNCOUT VCC VDDA
component class "Mounting Holes": H7 H8 H9 H10
component class Header: J2 J100 J200
component class 58VinMax3v320A&5v15A: C1 C2 C3 C4 C5 C6 C7 C8 C9 C10 C11 C12 C13 C14 C15 C16 C17 C18 C19 C20 C21 C22 C23 C24 C25 C26 C27 C28 C29 C30 C31 C32 C33 C34 C35 C36 C37 C38 C39 C40 C41 C42 C43 C44 C45 C46 C47 C48 C49 C50 C51 C52 C53 C54 C55 C56 C57 C58 C59 C60 C61 C62 C63 C64 C65 C66 C67 C68 C69 C70 C71 C72 C73 C74 C75 C76 C77 C78 C79 C80 C81 C82 C83 C84 C85 C86 C87 C88 C89 C90 C91 C92 C93 C94 C95 C96 C97 C101 C102 C201 C202 Ccomp1 Ccomp2 Ccs1 Ccs2 Cdith Chf1 Chf2 Cpi1 Cpi2 Cpi3 Cpi4 Cpi5 Cpi6 Cpi7 Cpi8 Cpi9 Cres Csns5V Csnu1 Csnu2 Css1 Css2 D1 D2 D3 D4 D5 J1 J2 J11 J33 J50 J100 J101 J102 J200 J201 J202 L1 L2 Lcm Lpi Lpi-hf NT1 NTv1 NTv2 Q1 Q2 Q3 Q4 Q100 Q200 R1 R2 R3 R4 R5 R6 R7 R8 R9 R10 R11 R12 R13 R100 R101 R102 R103 R104 R200 R201 R202 R203 R204 Rbode1 Rbode2 Rcomp1 Rcomp2 Rcs1 Rcs2 Rd1 Rd2 Rdiv5-b Rdiv5-t Rdivb1 Rdivb2 Rdivt1 Rdivt2 Ren1 Ren2 Rfb3-1 Rmode Rpg1 Rpg2 Rsnu1 Rsnu2 Rt TP1 TP2 TP3 TP4 TP5 TP6 TP8 TP9 TP11 TP12 TP13 TP14 TP15 TP16 TPsns5V U1
component class Logo: Logo3
component class PMP23452_Hardware&misc: FID1 FID2 FID3 H3 H4 H5 H6 H7 H8 H9 H10 Logo1 LOGO2 Logo3 Logo4 Logo5 ZZ1 ZZ2 ZZ3 ZZ7
component class FiducialMark: FID1 FID2 FID3
component class AssemblyNote: ZZ1 ZZ2 ZZ3 ZZ7

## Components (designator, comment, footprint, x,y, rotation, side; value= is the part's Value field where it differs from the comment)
C1 "GCM21BR71E225KA73L" 0805_HV 1650.79,2456.46 r270 top value=2.2uF
C2 "GCM21BR71E225KA73L" 0805_HV 1745.28,2456.46 r270 top value=2.2uF
C3 "CGA5L2X7R2A474K160AA" 1206_180M 1996,2650.79 r0 top value=0.47uF
C4 "GCM188R71C474KA55D" 0603 1722.64,2941.2 r270 top value=0.47uF
C5 "GCM21BR71E225KA73L" 0805_HV 1439.74,2694.74 r180 top value=2.2uF
C6 "CGA3E2X7R1E104K080AA" 0603 1863.79,2535.07 r180 top value=0.1uF
C7 "CGA3E2X7R1E104K080AA" 0603 1501.14,2538.7 r0 top value=0.1uF
C8 "CGA6P1X7R1N106M250AC" 1210_280 2744.61,2736.17 r0 bottom value=10uF
C9 "CGA6P1X7R1N106M250AC" 1210_280 2744.61,2867.25 r0 bottom value=10uF
C10 "EEHZC1K470P" SM_RADIAL_10BMM 2693.94,3430 r90 top value=56uF
C11 "CGA6P1X7R1N106M250AC" 1210_280 2744.61,2736.17 r0 top value=10uF
C12 "CGA6P1X7R1N106M250AC" 1210_280 2744.61,2867.25 r0 top value=10uF
C13 "CGA6P1X7R1N106M250AC" 1210_280 2744.61,2994.88 r0 top value=10uF
C14 "CGA6P1X7R1N106M250AC" 1210_280 2557.63,2990.9 r180 top value=10uF
C15 "CGA6P1X7R1N106M250AC" 1210_280 3735,1590 r270 top value=10uF
C16 "CGA4J2X7R2A104K125AA" 0805_HV 2570.71,2871.5 r180 top value=0.1uF
C17 "CGA3E2X7R2A103K080AA" 0603 2570.71,2788.58 r180 top value=0.01uF
C18 "CGA3E2X7R2A102K080AA" 0603 2570.71,2718.7 r180 top value=1000pF
C19 "CGA6P1X7R1N106M250AC" 1210_280 2744.61,2994.88 r0 bottom value=10uF
C20 "EEHZC1K470P" SM_RADIAL_10BMM 750,3435.98 r90 top value=56uF
C21 "CGA6P1X7R1N106M250AC" 1210_280 865,2737.49 r0 top value=10uF
C22 "CGA6P1X7R1N106M250AC" 1210_280 865,2870.74 r0 top value=10uF
C23 "CGA6P1X7R1N106M250AC" 1210_280 865,3007.32 r0 top value=10uF
C24 "CGA6P1X7R1N106M250AC" 1210_280 3875,1590 r270 top value=10uF
C25 "CGA6P1X7R1N106M250AC" 1210_280 676.24,2993.09 r180 top value=10uF
C26 "CGA4J2X7R2A104K125AA" 0805_HV 690,2873.5 r180 top value=0.1uF
C27 "CGA3E2X7R2A103K080AA" 0603 690,2792.01 r180 top value=0.01uF
C28 "CGA3E2X7R2A102K080AA" 0603 690,2722.01 r180 top value=1000pF
C29 "CGA6P1X7R1N106M250AC" 1210_280 2557.26,2990.9 r180 bottom value=10uF
C30 "CGA3E2X7R1E104K080AA" 0603L 3321.5,1425.51 r270 top value=0.1uF
C31 "GRM32ER71A476ME15L" 1210_270 2620,940 r270 bottom value=47uF
C32 "GRM32ER71A476ME15L" 1210_270 2430,940 r270 bottom value=47uF
C33 "GRM32ER71A476ME15L" 1210_270 2252,940.32 r270 top value=47uF
C34 "GRM32ER71A476ME15L" 1210_270 2830,940 r270 top value=47uF
C35 "GRM32ER71A476ME15L" 1210_270 2620,940 r270 top value=47uF
C36 "GRM32ER71A476ME15L" 1210_270 2430,940 r270 top value=47uF
C37 "GRM32ER71A476ME15L" 1210_270 3230,1170 r270 bottom value=47uF
C38 "GRM32ER71A476ME15L" 1210_270 3030,1170 r270 bottom value=47uF
C39 "GRM32ER71A476ME15L" 1210_270 2830,1170 r270 bottom value=47uF
C40 "GRM32ER71A476ME15L" 1210_270 2620,1170 r270 bottom value=47uF
C41 "GRM32ER71A476ME15L" 1210_270 2252,939.36 r270 bottom value=47uF
C42 "GRM32ER71A476ME15L" 1210_270 2430,1170 r270 bottom value=47uF
C43 "GRM32ER71A476ME15L" 1210_270 2230,1170 r270 bottom value=47uF
C44 "GRM32ER71A476ME15L" 1210_270 3230,1170 r270 top value=47uF
C45 "GRM32ER71A476ME15L" 1210_270 3030,1170 r270 top value=47uF
C46 "GRM32ER71A476ME15L" 1210_270 2830,1170 r270 top value=47uF
C47 "GRM32ER71A476ME15L" 1210_270 2620,1170 r270 top value=47uF
C48 "GRM32ER71A476ME15L" 1210_270 2430,1170 r270 top value=47uF
C49 "GRM32ER71A476ME15L" 1210_270 2230,1170 r270 top value=47uF
C50 "GRM32ER71A476ME15L" 1210_270 3230,1430 r270 bottom value=47uF
C51 "GRM32ER71A476ME15L" 1210_270 3030,1430 r270 bottom value=47uF
C52 "GRM32ER71A476ME15L" 1210_270 2830,1430 r270 bottom value=47uF
C53 "GRM32ER71A476ME15L" 1210_270 2830,940 r270 bottom value=47uF
C54 "GRM32ER71A476ME15L" 1210_270 2620,1430 r270 bottom value=47uF
C55 "GRM32ER71A476ME15L" 1210_270 2430,1430 r270 bottom value=47uF
C56 "GRM32ER71A476ME15L" 1210_270 2230,1430 r270 bottom value=47uF
C57 "GRM32ER71A476ME15L" 1210_270 3230,1430 r270 top value=47uF
C58 "GRM32ER71A476ME15L" 1210_270 3030,1430 r270 top value=47uF
C59 "GRM32ER71A476ME15L" 1210_270 2830,1430 r270 top value=47uF
C60 "GRM32ER71A476ME15L" 1210_270 2620,1430 r270 top value=47uF
C61 "GRM32ER71A476ME15L" 1210_270 2430,1430 r270 top value=47uF
C62 "GRM32ER71A476ME15L" 1210_270 2230,1430 r270 top value=47uF
C63 "CGA3E2X7R1E104K080AA" 0603L 1280,1450 r270 top value=0.1uF
C64 "GRM32ER71A476ME15L" 1210_270 1170,1450 r270 top value=47uF
C65 "GRM32ER71A476ME15L" 1210_270 980,1450 r270 top value=47uF
C66 "GRM32ER71A476ME15L" 1210_270 790,1440 r270 top value=47uF
C67 "GRM32ER71A476ME15L" 1210_270 580,1440 r270 top value=47uF
C68 "GRM32ER71A476ME15L" 1210_270 370,1440 r270 top value=47uF
C69 "GRM32ER71A476ME15L" 1210_270 581,1163 r270 bottom value=47uF
C70 "GRM32ER71A476ME15L" 1210_270 363,1163 r270 bottom value=47uF
C71 "GRM32ER71A476ME15L" 1210_270 1170,1169 r270 top value=47uF
C72 "GRM32ER71A476ME15L" 1210_270 979,1169 r270 top value=47uF
C73 "GRM32ER71A476ME15L" 1210_270 792,1165 r270 top value=47uF
C74 "GRM32ER71A476ME15L" 1210_270 580,1162 r270 top value=47uF
C75 "GRM32ER71A476ME15L" 1210_270 363,1163 r270 top value=47uF
C76 "GRM32ER71A476ME15L" 1210_270 1167,1451 r270 bottom value=47uF
C77 "GRM32ER71A476ME15L" 1210_270 981,1451 r270 bottom value=47uF
C78 "GRM32ER71A476ME15L" 1210_270 792,1440 r270 bottom value=47uF
C79 "GRM32ER71A476ME15L" 1210_270 580,1438 r270 bottom value=47uF
C80 "GRM32ER71A476ME15L" 1210_270 369,1440 r270 bottom value=47uF
C81 "GRM32ER71A476ME15L" 1210_270 1000,917 r270 bottom value=47uF
C82 "GRM32ER71A476ME15L" 1210_270 800,916 r270 bottom value=47uF
C83 "GRM32ER71A476ME15L" 1210_270 575,909 r270 bottom value=47uF
C84 "GRM32ER71A476ME15L" 1210_270 373,913 r270 bottom value=47uF
C85 "GRM32ER71A476ME15L" 1210_270 1012,913 r270 top value=47uF
C86 "GRM32ER71A476ME15L" 1210_270 801,913 r270 top value=47uF
C87 "GRM32ER71A476ME15L" 1210_270 575,912 r270 top value=47uF
C88 "GRM32ER71A476ME15L" 1210_270 371,912 r270 top value=47uF
C89 "GRM32ER71A476ME15L" 1210_270 1180,1181 r270 bottom value=47uF
C90 "GRM32ER71A476ME15L" 1210_270 986,1174 r270 bottom value=47uF
C91 "GRM32ER71A476ME15L" 1210_270 792,1165 r270 bottom value=47uF
C92 "CGA6P1X7R1N106M250AC" 1210_280 3735,1590 r270 bottom value=10uF
C93 "CGA6P1X7R1N106M250AC" 1210_280 865,2737.49 r0 bottom value=10uF
C94 "CGA6P1X7R1N106M250AC" 1210_280 865,2870.74 r0 bottom value=10uF
C95 "CGA6P1X7R1N106M250AC" 1210_280 865,3006.38 r0 bottom value=10uF
C96 "CGA6P1X7R1N106M250AC" 1210_280 3875,1590 r270 bottom value=10uF
C97 "CGA6P1X7R1N106M250AC" 1210_280 676.24,2993.09 r180 bottom value=10uF
C101 "CGA3E2X7R1E104K080AA" 0603 2930,936.9 r90 top value=0.1uF
C102 "CGA3E2X7R1E104K080AA" 0603 3012.97,464.01 r90 top value=0.1uF
C201 "CGA3E2X7R1E104K080AA" 0603 1112,915.17 r90 top value=0.1uF
C202 "CGA3E2X7R1E104K080AA" 0603 1191.76,454.63 r90 top value=0.1uF
Ccomp1 "CGA3E2X7R2A682K080AA" 0603 2065.5,2789.97 r90 top value=6800pF
Ccomp2 "CGA3E2X7R2A682K080AA" 0603 1380.84,2815.17 r90 top value=6800pF
Ccs1 "C0603C222K5RAC" 0603 1887.22,2729.53 r270 bottom value=2200pF
Ccs2 "C0603C222K5RAC" 0603 1491.22,2738.46 r90 bottom value=2200pF
Cdith "GRM188R72A103KA01D" 0603 1591.73,2944.21 r90 top value=0.01uF
Chf1 "DNP" 0603 1947.2,2834 r0 top value=47pF
Chf2 "DNP" 0603 1477.89,2847.12 r180 top value=47pF
Cpi1 "CGA6P1X7R1N106M250AC" 1210_280 3772,3476 r180 bottom value=10uF
Cpi2 "CGA6P1X7R1N106M250AC" 1210_280 3772,3346 r180 bottom value=10uF
Cpi3 "CGA6P1X7R1N106M250AC" 1210_280 3740,2630 r180 bottom value=10uF
Cpi4 "CGA6P1X7R1N106M250AC" 1210_280 3740,2495 r180 bottom value=10uF
Cpi5 "CGA6P1X7R1N106M250AC" 1210_280 3740,2630 r180 top value=10uF
Cpi6 "CGA6P1X7R1N106M250AC" 1210_280 3740,2495 r180 top value=10uF
Cpi7 "CGA4J2X7R2A104K125AA" 0805_HV 3750,3587.2 r180 bottom value=0.1uF
Cpi8 "CGA3E2X7R2A103K080AA" 0603 3750,3663.9 r180 bottom value=0.01uF
Cpi9 "CGA3E2X7R2A102K080AA" 0603 3750,3730 r180 bottom value=1000pF
Cres "CL10B224KO8VPNC" 0603 1785.28,2945.12 r90 top value=0.22uF
Csns5V "CGA3E2X7R1E104K080AA" 0603 207.21,506.99 r90 top value=0.1uF
Csnu1 "GRM1885C2A270JA01D" 0603 2229.78,2461.34 r90 top value=27pF
Csnu2 "GRM1885C2A270JA01D" 0603 387,2425 r90 top value=27pF
Css1 "CGA3E2X7R1E104K080AA" 0603 1847.49,2901.25 r90 top value=0.1uF
Css2 "CGA3E2X7R1E104K080AA" 0603 1524.47,2944.21 r90 top value=0.1uF
D1 "BAT46W-E3-08" SOD-123 1881.67,2450.45 r180 top value=100V
D2 "BAT46LS-QYL" FP-BAT46LS-QYL_DFN1006BD-2-0 1932.25,2901.25 r0 top
D3 "BAT46W-E3-08" SOD-123 1497.2,2455.34 r0 top value=100V
D4 "BAT46LS-QYL" FP-BAT46LS-QYL_DFN1006BD-2-0 1459.2,2911.1 r270 top
D5 "BAT46LS-QYL" FP-BAT46LS-QYL_DFN1006BD-2-0 1949.97,2650.87 r0 bottom
FID1 "Fiducial" Fiducial10-20 79,3380 r0 top
FID2 "Fiducial" Fiducial10-20 79.08,920 r0 top
FID3 "Fiducial" Fiducial10-20 3877,470 r0 top
H3 "1902C" Keystone_1902C 210,3786 r0 bottom
H4 "1902C" Keystone_1902C 3307,3800 r0 bottom
H5 "1902C" Keystone_1902C 210.21,204 r0 bottom
H6 "1902C" Keystone_1902C 3788,203 r0 bottom
H7 "NY PMS 440 0025 PH" "NY PMS 440 0025 PH" 210,3786 r0 top
H8 "NY PMS 440 0025 PH" "NY PMS 440 0025 PH" 3307,3800 r0 top
H9 "NY PMS 440 0025 PH" "NY PMS 440 0025 PH" 210.21,204 r0 top
H10 "NY PMS 440 0025 PH" "NY PMS 440 0025 PH" 3788,203 r0 top
J1 "1040" CONN_1040 1701,2291 r0 top
J2 "PBC12SABN" Sullins_PxC12SABN 1718.9,3810 r0 top
J11 "ED120/2DS" On-Shore_ED120_2DS 3740,3820 r180 top
J33 "ED120/4DS" On-Shore_ED120_4DS 2670,183.54 r0 top
J50 "ED120/4DS" On-Shore_ED120_4DS 880,173.68 r0 top
J100 "5-146261-1" CONN_5-146261-1 3271.29,317.79 r270 top
J101 "MMCX-J-P-H-ST-TH1" Samtec_MMCX-J-P-H-ST-TH1 3115,964 r0 top
J102 "MMCX-J-P-H-ST-TH1" Samtec_MMCX-J-P-H-ST-TH1 3138.1,633.43 r0 top
J200 "5-146261-1" CONN_5-146261-1 1459.07,318.51 r270 top
J201 "MMCX-J-P-H-ST-TH1" Samtec_MMCX-J-P-H-ST-TH1 1272.87,951.49 r0 top
J202 "MMCX-J-P-H-ST-TH1" Samtec_MMCX-J-P-H-ST-TH1 1324,616.8 r0 top
L1 "XAL1350-132MED" FP-XAL1350-132MED_SMT_INDUCTOR_13MM0_14MM0-MFG 2554.27,2010.71 r90 top value=1.3uH
L2 "XAL1350-222MEB" XAL1350 720,2020 r270 top value=2.2uH
Lcm "ACM1211-701-2PL-TL01" TDK_ACM1211 3750,3000 r180 bottom
Logo1 "CE Mark" CE_Mark_5mm 3711,642 r180 bottom
LOGO2 "CAUTION HOT SURFACE" IEC_HotSurface_Small 1700,2103.14 r0 top
Logo3 "Texas Instruments" TI_Stacked_Overlay_Small 2530,3576.3 r180 bottom
Logo4 "FCC disclaimer" FCC_disclaimer 63,1565 r270 bottom
Logo5 "WEEE logo" WEEE_Minimum 217,2102 r180 bottom
Lpi "XGL1060-103MEC" FP-XGL1060-103MEC_SMT2_10MM0_11MM3-MFG 3710,1916.5 r0 top value=10uH
Lpi-hf "HR2220V801R-10" 2220_390 3725,2293.84 r180 top value="800 ohm"
NT1 "Net-Tie" Net-Tie_10mil#1 1710,2783 r270 top net-tie
NTv1 "Net-Tie" Net-Tie_10mil#2 2557,1634 r270 top net-tie
NTv2 "Net-Tie" Net-Tie_10mil#2 730.75,1650 r270 top net-tie
Q1 "NVMFS6H848NLWFT1G" FP-NVMFS6H848NLWFT1G_DFNW5-5x6-MFG 2654.84,2518.17 r0 top
Q2 "NVMFS6H824NLWFT1G" FP-NVMFS6H824NLWFT1G_DFNW5-5x6-MFG 2383.43,2520.04 r180 top
Q3 "NVMFS6H852NLWFT1G" FP-NVMFS6H852NLWFT1G_DFN5-MFG 840,2520 r0 top
Q4 "NVMFS6H824NLWFT1G" FP-NVMFS6H824NLWFT1G_DFNW5-5x6-MFG 566,2520.2 r180 top
Q100 "CSD17579Q3A" DNH0008A 2830,653.11 r90 top value=30V
Q200 "CSD17579Q3A" DNH0008A 1008.05,656.99 r90 top value=30V
R1 "WSL10202L000FEA" FP-WSL10202L000FEA_1020-MFG 2560,1650 r90 top value=2m
R2 "WSL10202L000FEA" FP-WSL10202L000FEA_1020-MFG 730.75,1664.29 r270 top value=2m
R3 "RC0603FR-071RL" 0603 1441.15,2613.85 r180 top value=1.00
R4 "CRCW06030000Z0EA" 0603 2873,2362.68 r90 top value=0
R5 "CRCW06030000Z0EA" 0603 1057,2425.87 r180 top value=0
R6 "CRCW0603100KFKEA" 0603 2803.74,2363.93 r90 top value=100k
R7 "CRCW06030000Z0EA" 0603 2936.5,2362.68 r90 top value=0
R8 "CRCW06030000Z0EA" 0603 1056,2501.34 r180 top value=0
R9 "CRCW06030000Z0EA" 0603 464.09,2734.99 r270 top value=0
R10 "CRCW06030000Z0EA" 0603 2241.77,2758.47 r270 top value=0
R11 "CRCW0603100KFKEA" 0603 2310.34,2741.5 r270 top value=100k
R12 "CRCW0603100KFKEA" 0603 391,2734.99 r270 top value=100k
R13 "CRCW0603100KFKEA" 0603 1056,2347.71 r180 top value=100k
R100 "RCWE1020R100FKEA" FP-RCWE1020R115FKEA_1020-MFG 2862.63,488.64 r90 top
R101 "CRCW060349R9FKEA" 0603 2964.87,968.4 r180 bottom value=49.9
R102 "CRCW060349R9FKEA" 0603 3013.31,599.88 r90 top value=49.9
R103 "CRCW06031R00JNEA" 0603 3172.29,407.78 r270 top value=1.0
R104 "CRCW060310K0FKEA" 0603 3169.92,270.55 r90 top value=10.0k
R200 "RCWE1020R100FKEA" FP-RCWE1020R115FKEA_1020-MFG 1040.72,480.15 r90 top
R201 "CRCW060349R9FKEA" 0603 1135,946.66 r180 bottom value=49.9
R202 "CRCW060349R9FKEA" 0603 1191.54,589.98 r90 top value=49.9
R203 "CRCW06031R00JNEA" 0603 1352.67,417.99 r270 top value=1.0
R204 "CRCW060310K0FKEA" 0603 1353.04,275.62 r90 top value=10.0k
Rbode1 "CRCW060310R0JNEAHP" 0603 2029,3035 r0 bottom value=10
Rbode2 "CRCW060310R0JNEAHP" 0603 1397.26,3315.13 r0 top value=10
Rcomp1 "CRCW060313K0FKEA" 0603 1964,2760 r180 top value=13.0k
Rcomp2 "CRCW060311K3FKEA" 0603 1476.81,2778.27 r0 top value=11.3k
Rcs1 "CRCW0603100RFKEA" 0603 1985.13,2753.15 r0 bottom value=100
Rcs2 "CRCW0603100RFKEA" 0603 1380.84,2773 r180 bottom value=100
Rd1 "SR733ATTE1R00F" FP-SR733ATTE1R00F_2512-MFG 2406.13,3411.05 r270 top value=1
Rd2 "SR733ATTE1R00F" FP-SR733ATTE1R00F_2512-MFG 1047,3431 r90 top value=1
Rdiv5-b "CRCW0603200KFKEA" 0603 270.48,506.99 r90 top value=200k
Rdiv5-t "CRCW0603200KFKEA" 0603 207.21,636.76 r90 top value=200k
Rdivb1 "CRCW060322K1FKEA" 0603 2037.4,2901.25 r0 top value=22.1k
Rdivb2 "CRCW060313K7FKEA" 0603 1445,3040.38 r90 top value=13.7k
Rdivt1 "CRCW0603100KFKEA" 0603 1997.53,2930.92 r90 bottom value=100k
Rdivt2 "CRCW0603100KFKEA" 0603 1344,3092 r180 top value=100k
Ren1 "CRCW0603549KFKEA" 0603 2153.5,3698.5 r0 top value=549k
Ren2 "CRCW0603549KFKEA" 0603 1275,3677 r270 top value=549k
Rfb3-1 "CRCW06030000Z0EA" 0603 2067.53,2930.92 r90 bottom value=0
Rmode "CRCW06030000Z0EA" 0603 1768.9,2941.77 r270 bottom value=0
Rpg1 "CRCW060310K0FKEA" 0603 1968,3663 r270 top value=10.0k
Rpg2 "CRCW060310K0FKEA" 0603 1468.62,3667 r270 top value=10.0k
Rsnu1 "CRCW08051R00JNEA" 0805_HV 2221.3,2610.87 r270 top value=1.0
Rsnu2 "CRCW08051R00JNEA" 0805_HV 391,2570.69 r270 top value=1.0
Rt "CRCW060397K6FKEA" 0603 1654.72,2943.7 r270 top value=97.6k
TP1 "1598-2" Keystone1598-2 3056,3342 r0 top
TP2 "1598-2" Keystone1598-2 2697,3824 r0 top
TP3 "5015" Testpoint_Keystone_Miniature 2147,132 r90 top
TP4 "1598-2" Keystone1598-2 2166.85,539.82 r0 top
TP5 "1598-2" Keystone1598-2 1611,113 r0 top
TP6 "5015" Testpoint_Keystone_Miniature 3187,95 r0 top
TP8 "1598-2" Keystone1598-2 445,504.49 r0 top
TP9 "1598-2" Keystone1598-2 3484.48,144.28 r0 top
TP11 "5010" Keystone5010 2105.76,3124.96 r0 top
TP12 "5012" Keystone5012 1946.14,3124.96 r0 top
TP13 "5011" Keystone5011 1788.66,3206 r0 top
TP14 "5010" Keystone5010 1484.52,3206 r0 top
TP15 "5012" Keystone5012 1311,3206 r0 top
TP16 "5011" Keystone5011 1644.29,3146 r0 top
TPsns5V "5003" Keystone5003 100.01,534.37 r90 top
U1 "LM5143QRHARQ1" RHA0040N-MFG 1700,2700 r0 top locked
ZZ1 "These assemblies are ESD sensitive, ESD precautions shall be observed." AssemblyNote 385,4538 r0 top
ZZ2 "These assemblies must be clean and free from flux and all contaminants. Use of no clean flux is not acceptable." AssemblyNote 385,4429.11 r0 top
ZZ3 "These assemblies must comply with workmanship standards IPC-A-610 Class 2, unless otherwise specified." AssemblyNote 385,4340.56 r0 top
ZZ7 "Place Shunt Jumper SH-J1 onto J2 onto pins 6-7 (VDDA - DEMB-SYNCIN)" AssemblyNote 383,4236 r0 top

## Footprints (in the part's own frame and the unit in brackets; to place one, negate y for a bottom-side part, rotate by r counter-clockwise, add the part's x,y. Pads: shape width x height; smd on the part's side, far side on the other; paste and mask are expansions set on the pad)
0603 [mm] "0603 from SM-752 data"
  rect 1x0.95 smd: 1(-0.8,0) 2(0.8,0)
  silkscreen extent -1.52,-0.69 1.52,0.69, body extent -0.87,-0.47 0.87,0.47, height 1
0603L [mm] "0603 from SM-752 data"
  rect 0.8x0.85 smd: 1(-0.7,0) 2(0.7,0)
  silkscreen extent -0.07,-0.33 0.07,0.33, body extent -0.87,-0.47 0.87,0.47, height 1
0805_HV [mil] "0805 with 30mil clearance between pads"
  rect 50x63 smd: 1(-40,0) 2(40,0)
  silkscreen extent -74,-40 74,40, body extent -43,-29 43,29, height 57
1206_180M [mm] "1206_180"
  rect 1.5x1.95 smd: 1(-1.55,0) 2(1.55,0)
  silkscreen extent -2.76,-1.44 2.76,1.44, body extent -1.75,-0.95 1.75,0.95, height 1.8
1210_270 [mm] "1210"
  rect 1.3x2.7 smd: 1(-1.45,0) 2(1.45,0)
  silkscreen extent -2.32,-1.57 2.32,1.57, body extent -1.7,-1.35 1.7,1.35, height 2.7
1210_280 [mm] "SMD, 2-Leads, Body 3.6x2.8mm, Height 2.8mm"
  rect 1.1x2.2 smd: 1(-1.65,0) 2(1.65,0)
  silkscreen extent -0.84,-1.4 0.84,1.4, body extent -1.8,-1.4 1.8,1.4, height 2.8
2220_390 [mm] "Laird recommended land pattern"
  rrect3% 3.07x6.1 smd: 1(-3.06,0) 2(3.06,0)
  silkscreen extent -1.3,-3 1.3,3, body extent -2.8,-2.54 2.79,2.54, height 3.9
AssemblyNote [mil] "Assembly Note"
CE_Mark_5mm [mil] "Minimum text height for CE Mark"
  silkscreen extent -138,-98 138,98
CONN_5-146261-1 [mm] "Sullins"
  rect 1.5x1.5 hole 1.02: 1(-1.27,0)
  round 1.5 hole 1.02: 2(1.27,0)
  silkscreen extent -3.68,-1.27 2.54,1.27, body extent -2.51,-1.27 2.51,1.27, height 10.87
CONN_1040 [mil] "Test Point, PC  test point Terminal"
  round 75 hole 52: 1(0,0)
  body extent -55,-12 55,13, height 276
DNH0008A [mm] "VSONP-8"
  rrect50% 0.7x0.4 smd paste-0.05 mask-0.05: 1(-1.55,0.975) 2(-1.55,0.325) 3(-1.55,-0.325) 4(-1.55,-0.975) 5(1.55,-0.975) 6(1.55,-0.325) 7(1.55,0.325) 8(1.55,0.975)
  rrect4% 2.51x2.55 smd paste-1.5 mask-1.5: 9(0.645,0)
  rrect14% 0.705x1.125 on Top Paste: 9A(-0.208,0.662) 9B(0.697,0.662) 9C(-0.208,-0.663) 9D(0.697,-0.663)
  silkscreen extent -1.62,-1.7 1.62,1.7, body extent -1.65,-1.66 1.65,1.66, height 0.91
FCC_disclaimer [mil]
Fiducial10-20 [mm]
  round 1 smd mask+0.5: 1(0,0)
  Top Layer keep-out circle w1.178: c0,0 r0.5
FP-BAT46LS-QYL_DFN1006BD-2-0 [mm]
  rrect20% 0.5x0.7 smd paste-1000 mask+0: 1(-0.4,0) 2(0.4,0)
  silkscreen extent -1.32,-0.72 0.53,0.72, body extent -0.75,-0.45 0.75,0.45, height 0.25
FP-NVMFS6H824NLWFT1G_DFNW5-5x6-MFG [mm]
  rrect13% 0.75x1 smd paste+0 mask+0: 1(-1.905,-2.748) 2(-0.635,-2.748) 3(0.635,-2.748) 4(1.905,-2.748)
  round 3.631 smd paste+0 mask+0: 5-6(-0.121,0.735)
  Top Layer region: -2.28,-1.282 2.28,-1.282 2.28,-0.857 2.775,-0.857 2.775,0.048 2.28,0.048 2.28,3.247 1.53,3.247 1.53,2.772 -1.53,2.772 -1.53,3.247 -2.28,3.247 -2.28,0.048 -2.775,0.048 -2.775,-0.857 -2.28,-0.857 -2.28,-1.282
  silkscreen extent -2.8,-3.95 2.8,3.05, body extent -2.88,-3.35 2.88,3.35, height 0.25
FP-NVMFS6H848NLWFT1G_DFNW5-5x6-MFG [mm]
  rrect13% 0.75x1 smd paste+0 mask+0: 1(-1.905,-2.748) 2(-0.635,-2.748) 3(0.635,-2.748) 4(1.905,-2.748)
  round 3.631 smd paste+0 mask+0: 5-6(-0.05,0.735)
  Top Layer region: -2.28,-1.282 2.28,-1.282 2.28,-0.857 2.775,-0.857 2.775,0.048 2.28,0.048 2.28,3.247 1.53,3.247 1.53,2.772 -1.53,2.772 -1.53,3.247 -2.28,3.247 -2.28,0.048 -2.775,0.048 -2.775,-0.857 -2.28,-0.857 -2.28,-1.282
  silkscreen extent -2.8,-3.95 2.8,3.05, body extent -2.88,-3.35 2.88,3.35, height 0.25
FP-NVMFS6H852NLWFT1G_DFN5-MFG [mm]
  rrect13% 0.75x1 smd paste+0 mask+0: 1(-1.905,-2.748) 2(-0.635,-2.748) 3(0.635,-2.748) 4(1.905,-2.748)
  round 3.631 smd paste+0 mask+0: 5-6(-0.05,0.735)
  Top Layer region: -2.28,-1.282 -2.28,-0.857 -2.775,-0.857 -2.775,0.048 -2.28,0.048 -2.28,3.247 -1.53,3.247 -1.53,2.772 1.53,2.772 1.53,3.247 2.28,3.247 2.28,0.048 2.775,0.048 2.775,-0.857 2.28,-0.857 2.28,-1.282
  silkscreen extent -2.73,-3.95 2.73,3.05, body extent -2.88,-3.35 2.88,3.35, height 0.25
FP-RCWE1020R115FKEA_1020-MFG [mm]
  rrect8% 1.2x5.5 smd paste+0 mask+0: 1(-1.3,0) 2(1.3,0)
  silkscreen extent -0.32,-2.6 0.32,2.6, body extent -2,-2.85 2,2.85, height 0.25
FP-SR733ATTE1R00F_2512-MFG [mm]
  rrect6% 1.7x3 smd paste+0 mask+0: 1(-3.15,0) 2(3.15,0)
  silkscreen extent -1.92,-1.65 1.92,1.65, body extent -4.1,-1.75 4.1,1.75, height 0.25
FP-WSL10202L000FEA_1020-MFG [mm]
  rrect8% 1.25x5.65 smd paste+0 mask+0: 1(-1.125,0) 2(1.125,0)
  silkscreen extent -0.13,-2.6 0.13,2.6, body extent -1.85,-2.93 1.85,2.93, height 0.25
FP-XAL1350-132MED_SMT_INDUCTOR_13MM0_14MM0-MFG [mm]
  rrect3% 2.98x12 smd paste+0 mask+0: 1(-4.3,0) 2(4.3,0)
  silkscreen extent -6.6,-7.1 6.6,7.1, body extent -6.7,-7.2 6.7,7.2, height 0.25
FP-XGL1060-103MEC_SMT2_10MM0_11MM3-MFG [mm]
  rrect4% 2.38x8.5 smd paste+0 mask+0: 1(-3.325,0) 2(3.325,0)
  silkscreen extent -5.92,-5.9 5.25,5.9, body extent -5.35,-6 5.35,6, height 0.25
IEC_HotSurface_Small [mil]
  silkscreen extent -107,-93 107,92
Keystone1598-2 [mm] "Triple Turret"
  round 3.5 hole 2.5: 1(0,0)
  silkscreen extent -2.08,-2.08 2.08,2.08, body extent -1.6,-1.6 1.59,1.6, height 7.72
Keystone5003 [mil] "For Keystone 500x miniature loop terminals"
  round 80 hole 40: 1(0,0)
  silkscreen extent -52,-52 52,52, body extent -49,-49 49,49, height 182
Keystone5010 [mil] "Keystone Multipurpose loops"
  round 87 hole 63: 1(0,0)
  silkscreen extent -70,-70 70,70, body extent -63,-63 63,62, height 319
Keystone5011 [mil] "Keystone Multipurpose loops"
  round 87 hole 63: 1(0,0)
  silkscreen extent -70,-70 70,70, body extent -63,-63 63,62, height 319
Keystone5012 [mil] "Keystone Multipurpose loops"
  round 87 hole 63: 1(0,0)
  silkscreen extent -70,-70 70,70, body extent -63,-63 63,62, height 319
Keystone_1902C [mil] "Hex Standoff, 4-40 threaded, nylon"
  round 1 on Mech4: 0(0,0)
  body extent -145,-126 146,126, height 501
Net-Tie_10mil#1 [mil] "10mil net tie, no solder mask opening, no solder paste"
  rect 10x10 smd paste-5 mask-5: 1(-11.73,0.16) 2(10,0)
  Top Layer region: -6,5 6,5 6,-5 -6,-5
Net-Tie_10mil#2 [mil] "10mil net tie, no solder mask opening, no solder paste"
  rect 10x10 on Mid3 paste-5 mask-5: 1(-10,0) 2(10,0)
  Layer 4 region: -6,5 6,5 6,-5 -6,-5
"NY PMS 440 0025 PH" [mm] "4-40 nylon screw and mounting hole"
  round 8 hole 3.2 unplated: 1(0,0)
  body extent -3.3,-3.3 3.3,3.3, height 2.69
On-Shore_ED120_2DS [mm] "ONSHORE"
  rrect5% 2x2 hole 1.25: 1(-2.54,0)
  round 2 hole 1.25: 2(2.54,0)
  silkscreen extent -5.6,-4 5.12,5, body extent -5.78,-4 5.08,5, height 13
On-Shore_ED120_4DS [mm] "ONSHORE"
  rrect5% 2x2 hole 1.25: 1(-7.62,0)
  round 2 hole 1.25: 2(-2.54,0) 3(2.54,0) 4(7.62,0)
  silkscreen extent -10.68,-4 10.16,5, body extent -10.86,-4 10.16,5, height 13
RHA0040N-MFG [mm]
  rrect40% 0.6x0.25 smd paste+0 mask+0: 1(-2.9,2.25) 2(-2.9,1.75) 3(-2.9,1.25) 4(-2.9,0.75) 5(-2.9,0.25) 6(-2.9,-0.25) 7(-2.9,-0.75) 8(-2.9,-1.25) 9(-2.9,-1.75) 10(-2.9,-2.25) 21(2.9,-2.25) 22(2.9,-1.75) 23(2.9,-1.25) 24(2.9,-0.75) 25(2.9,-0.25) 26(2.9,0.25) 27(2.9,0.75) 28(2.9,1.25) 29(2.9,1.75) 30(2.9,2.25)
  rrect40% 0.25x0.6 smd paste+0 mask+0: 11(-2.25,-2.9) 12(-1.75,-2.9) 13(-1.25,-2.9) 14(-0.75,-2.9) 15(-0.25,-2.9) 16(0.25,-2.9) 17(0.75,-2.9) 18(1.25,-2.9) 19(1.75,-2.9) 20(2.25,-2.9) 31(2.25,2.9) 32(1.75,2.9) 33(1.25,2.9) 34(0.75,2.9) 35(0.25,2.9) 36(-0.25,2.9) 37(-0.75,2.9) 38(-1.25,2.9) 39(-1.75,2.9) 40(-2.25,2.9)
  rrect3% 3.3x3.3 smd paste-1000 mask+0: 41(0,0)
  silkscreen extent -3.87,-3.05 3.05,3.05, body extent -3.3,-3.3 3.3,3.3, height 0.25
Samtec_MMCX-J-P-H-ST-TH1 [mm] "Connector, MMCX, TH"
  round 1.2 hole 0.84: 1(0,0) 2(-1.27,1.27) 3(1.27,1.27) 4(1.27,-1.27) 5(-1.27,-1.27)
  silkscreen extent -1.75,-1.75 1.75,1.75, body extent -1.75,-1.75 1.75,1.75, height 4.35
SM_RADIAL_10BMM [mm] "Nichicon 10x10"
  rect 4x2.5 smd: 1(-4,0) 2(4,0)
  silkscreen extent -5.25,-5.25 5.25,5.25, body extent -5.25,-5.25 5.25,5.25, height 10.5
SOD-123 [mm] "On Semi recommended land pattern"
  rect 0.915x1.22 smd: 1(-1.637,0) 2(1.637,0)
  silkscreen extent -2.74,-1.17 2.03,1.17, body extent -1.93,-0.9 1.93,0.9, height 1.35
Sullins_PxC12SABN [mm] "Header, 2.54 mm, 12x1, TH"
  rect 1.55x1.55 hole 1.016: 1(-13.97,0)
  round 1.55 hole 1.016: 2(-11.43,0) 3(-8.89,0) 4(-6.35,0) 5(-3.81,0) 6(-1.27,0) 7(1.27,0) 8(3.81,0) 9(6.35,0) 10(8.89,0) 11(11.43,0) 12(13.97,0)
  silkscreen extent -15.49,-1.75 15.49,1.33, body extent -15.49,-1.33 15.49,1.33, height 8.71
TDK_ACM1211 [mm] "SMT, 4-Leads, Body 12x11mm"
  rect 2.7x3.2 smd: 1(-2.6,5.4) 2(2.6,5.4) 3(2.6,-5.4) 4(-2.6,-5.4)
  silkscreen extent -5.65,-6.15 5.65,6.15, body extent -5.65,-6.15 5.65,6.15, height 6
Testpoint_Keystone_Miniature [mil] "Miniature SMT test point"
  rect 135x70 smd: 1(0,0)
  silkscreen extent -78,-46 78,45, body extent -52,-20 52,20, height 61
TI_Stacked_Overlay_Small [mil]
  silkscreen extent -418,-98 418,98
WEEE_Minimum [mil] "WEEElie bin"
  silkscreen extent -95,-172 99,104
XAL1350 [mm] "COILCRAFT"
  rect 2.98x12 smd: 1(-4.3,0) 2(4.3,0)
  silkscreen extent -6.6,-7.1 6.6,7.1, body extent -6.6,-7.1 6.6,7.1, height 5.01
